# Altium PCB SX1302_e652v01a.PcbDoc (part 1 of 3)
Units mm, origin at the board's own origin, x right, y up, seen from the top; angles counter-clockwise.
Board outline 70.5 x 56 mm, 6 copper layers (Top Layer, MidLayer1 - GND, MidLayer2, MidLayer3, MidLayer4, Bottom Layer), stack 0.992 mm thick; 264 components, 191 nets, 862 pads, 1252 vias.
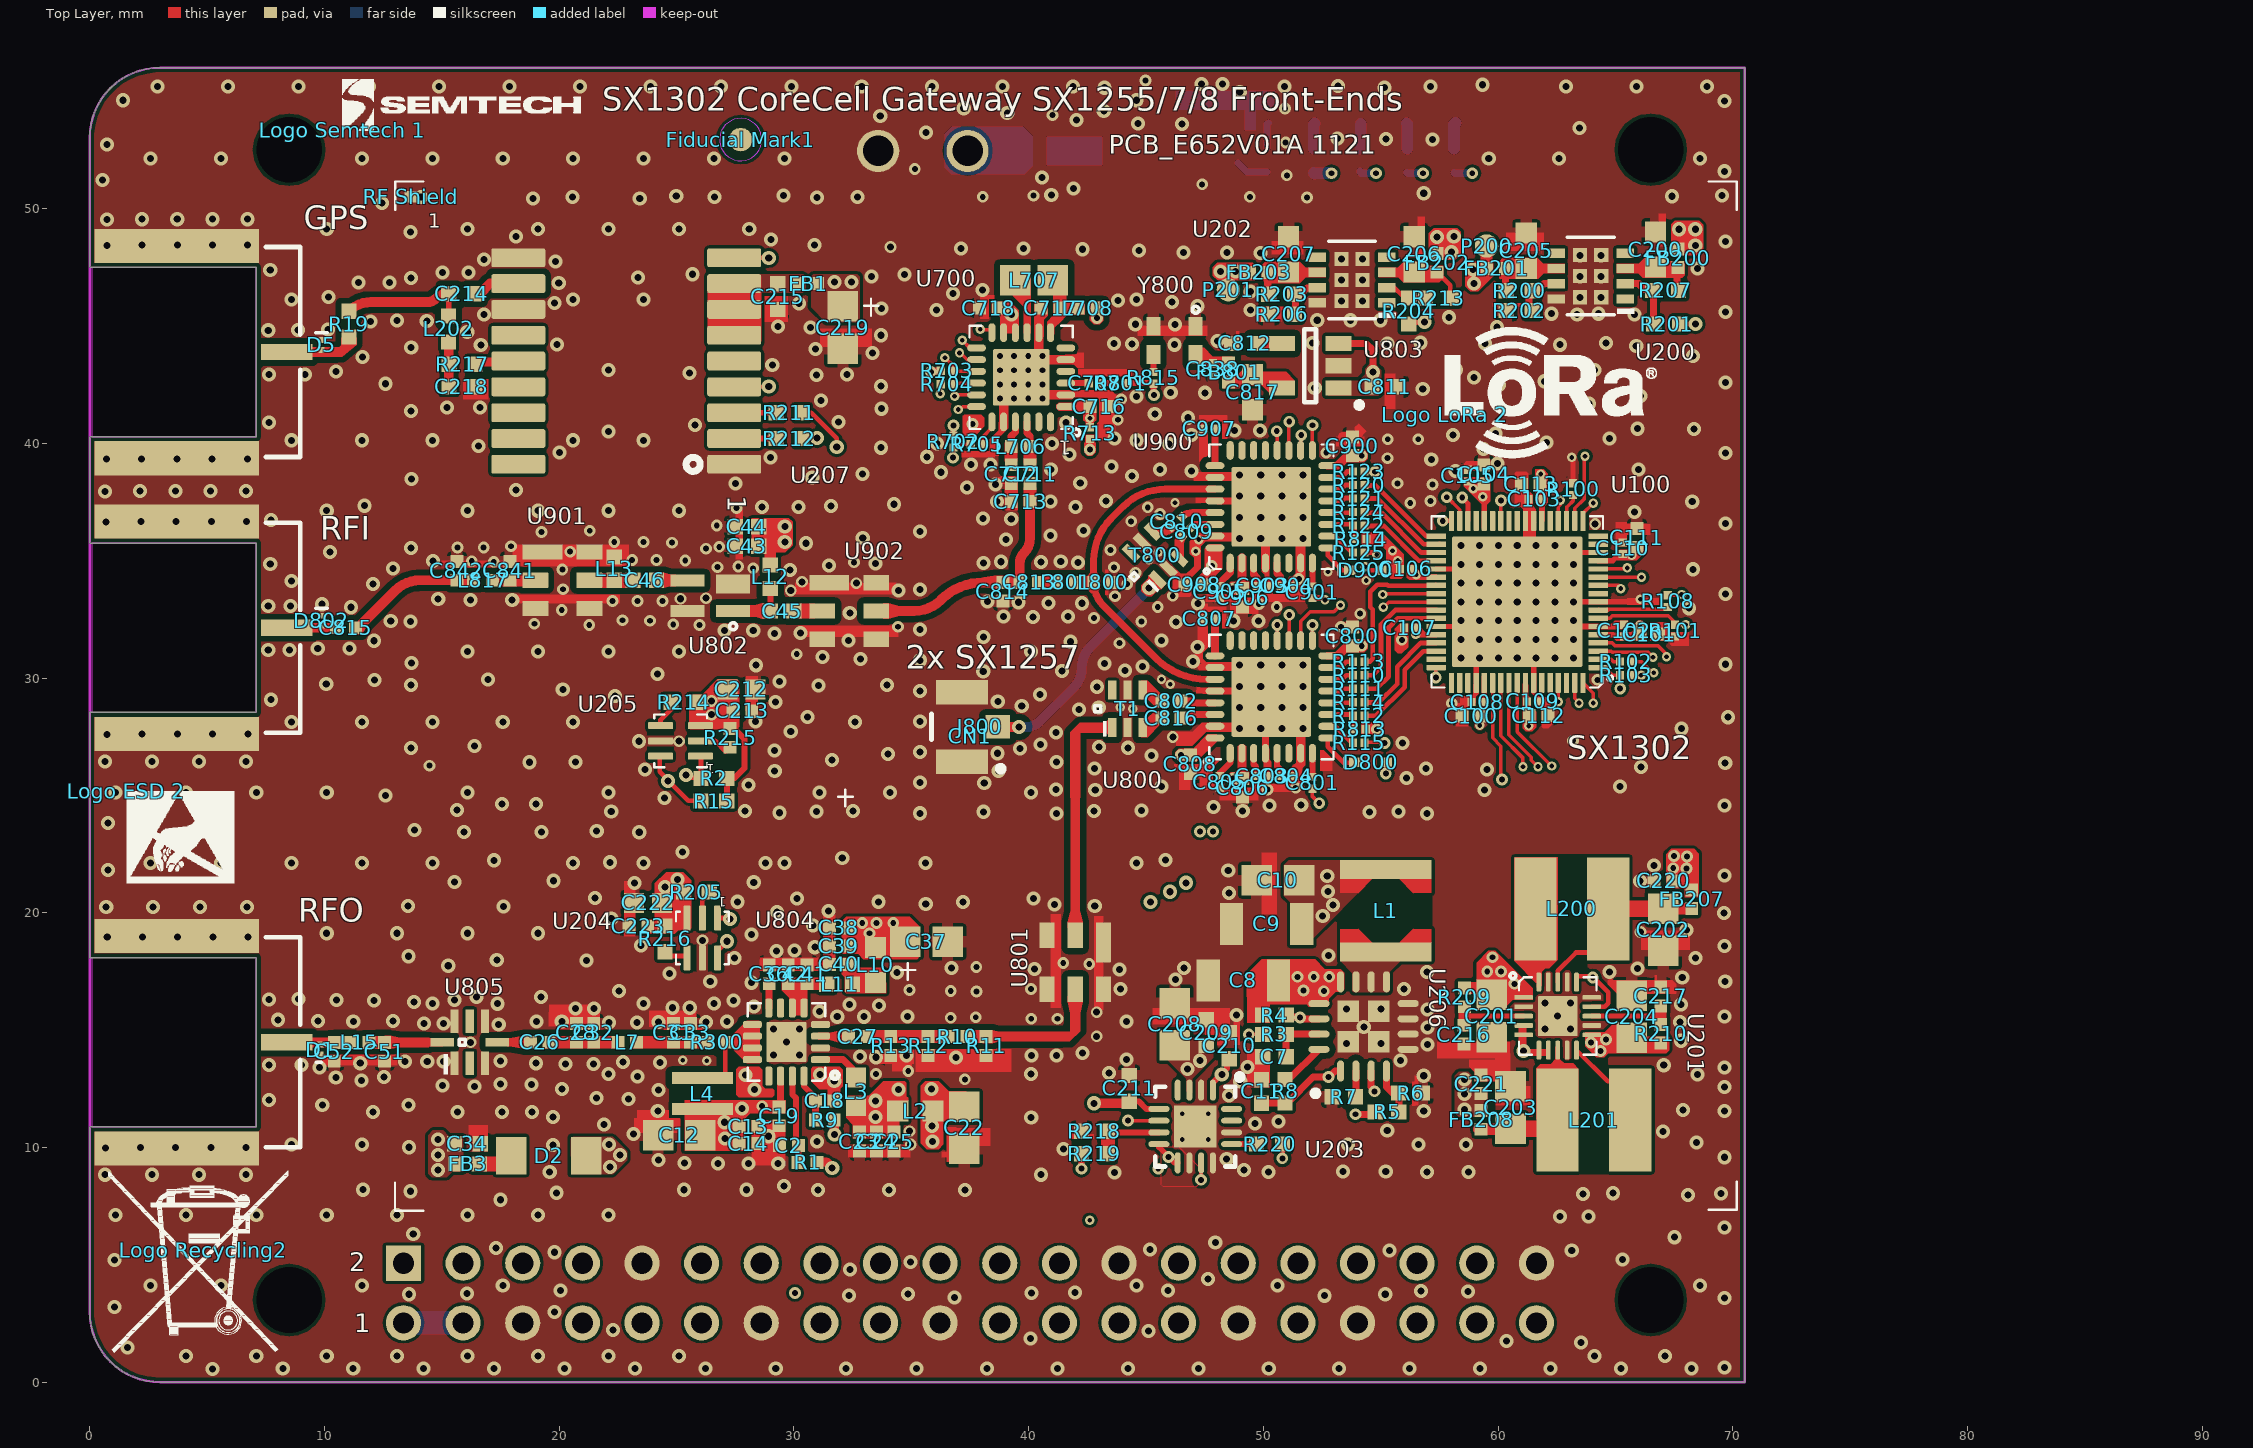
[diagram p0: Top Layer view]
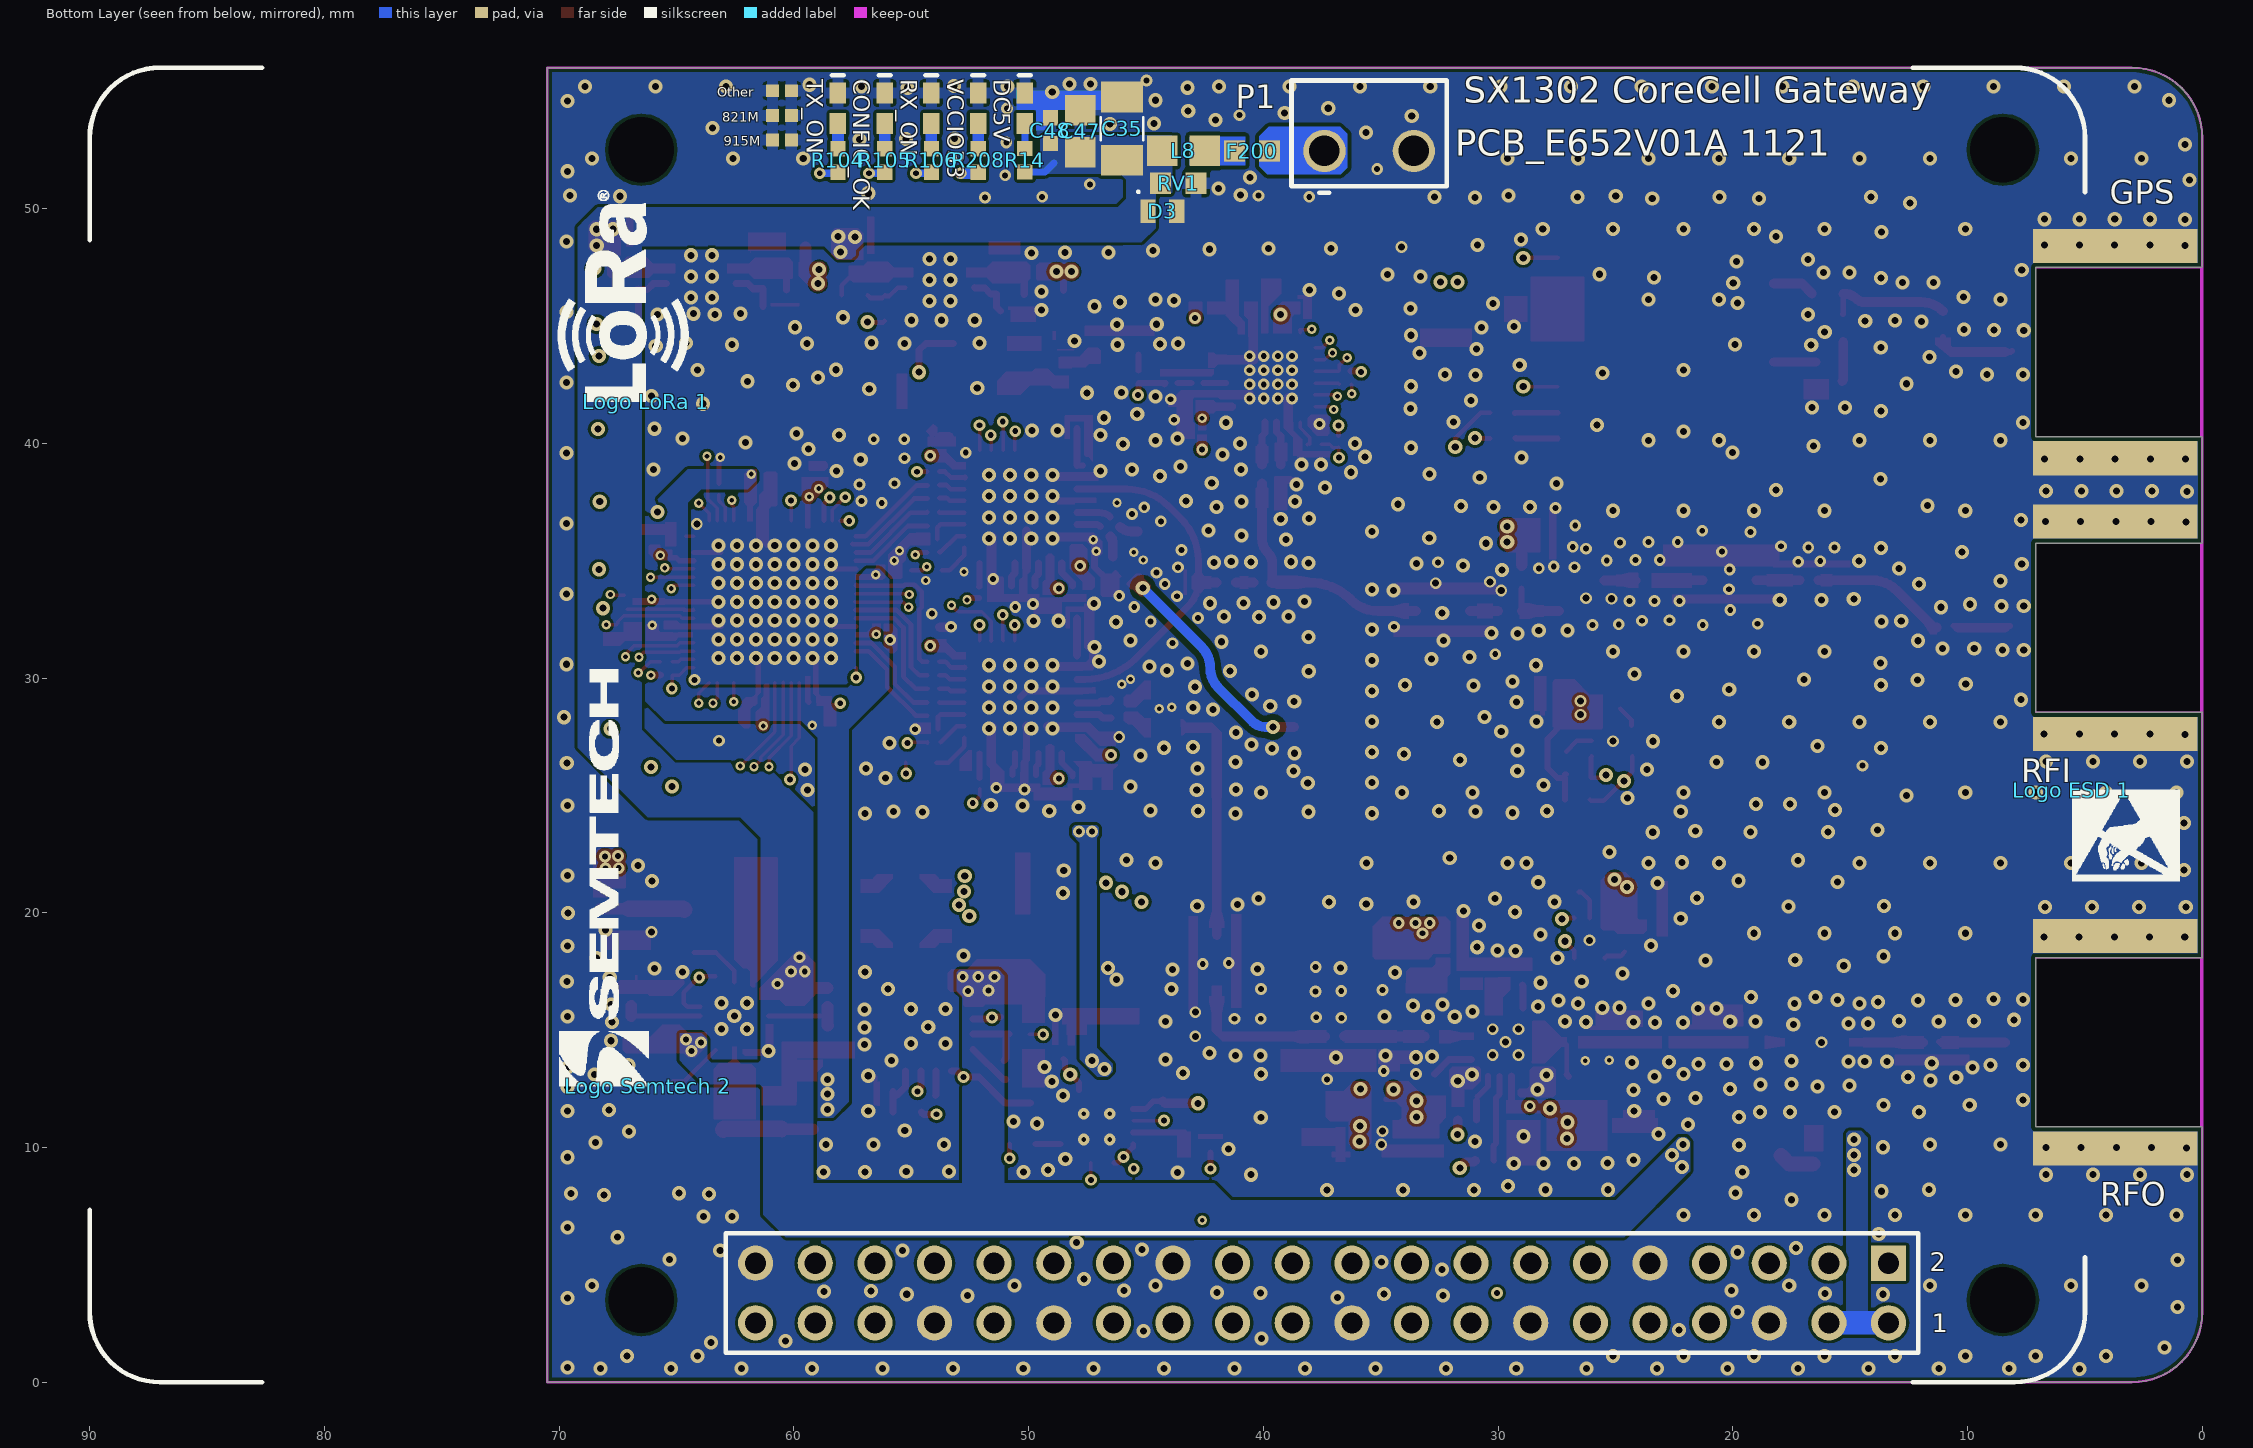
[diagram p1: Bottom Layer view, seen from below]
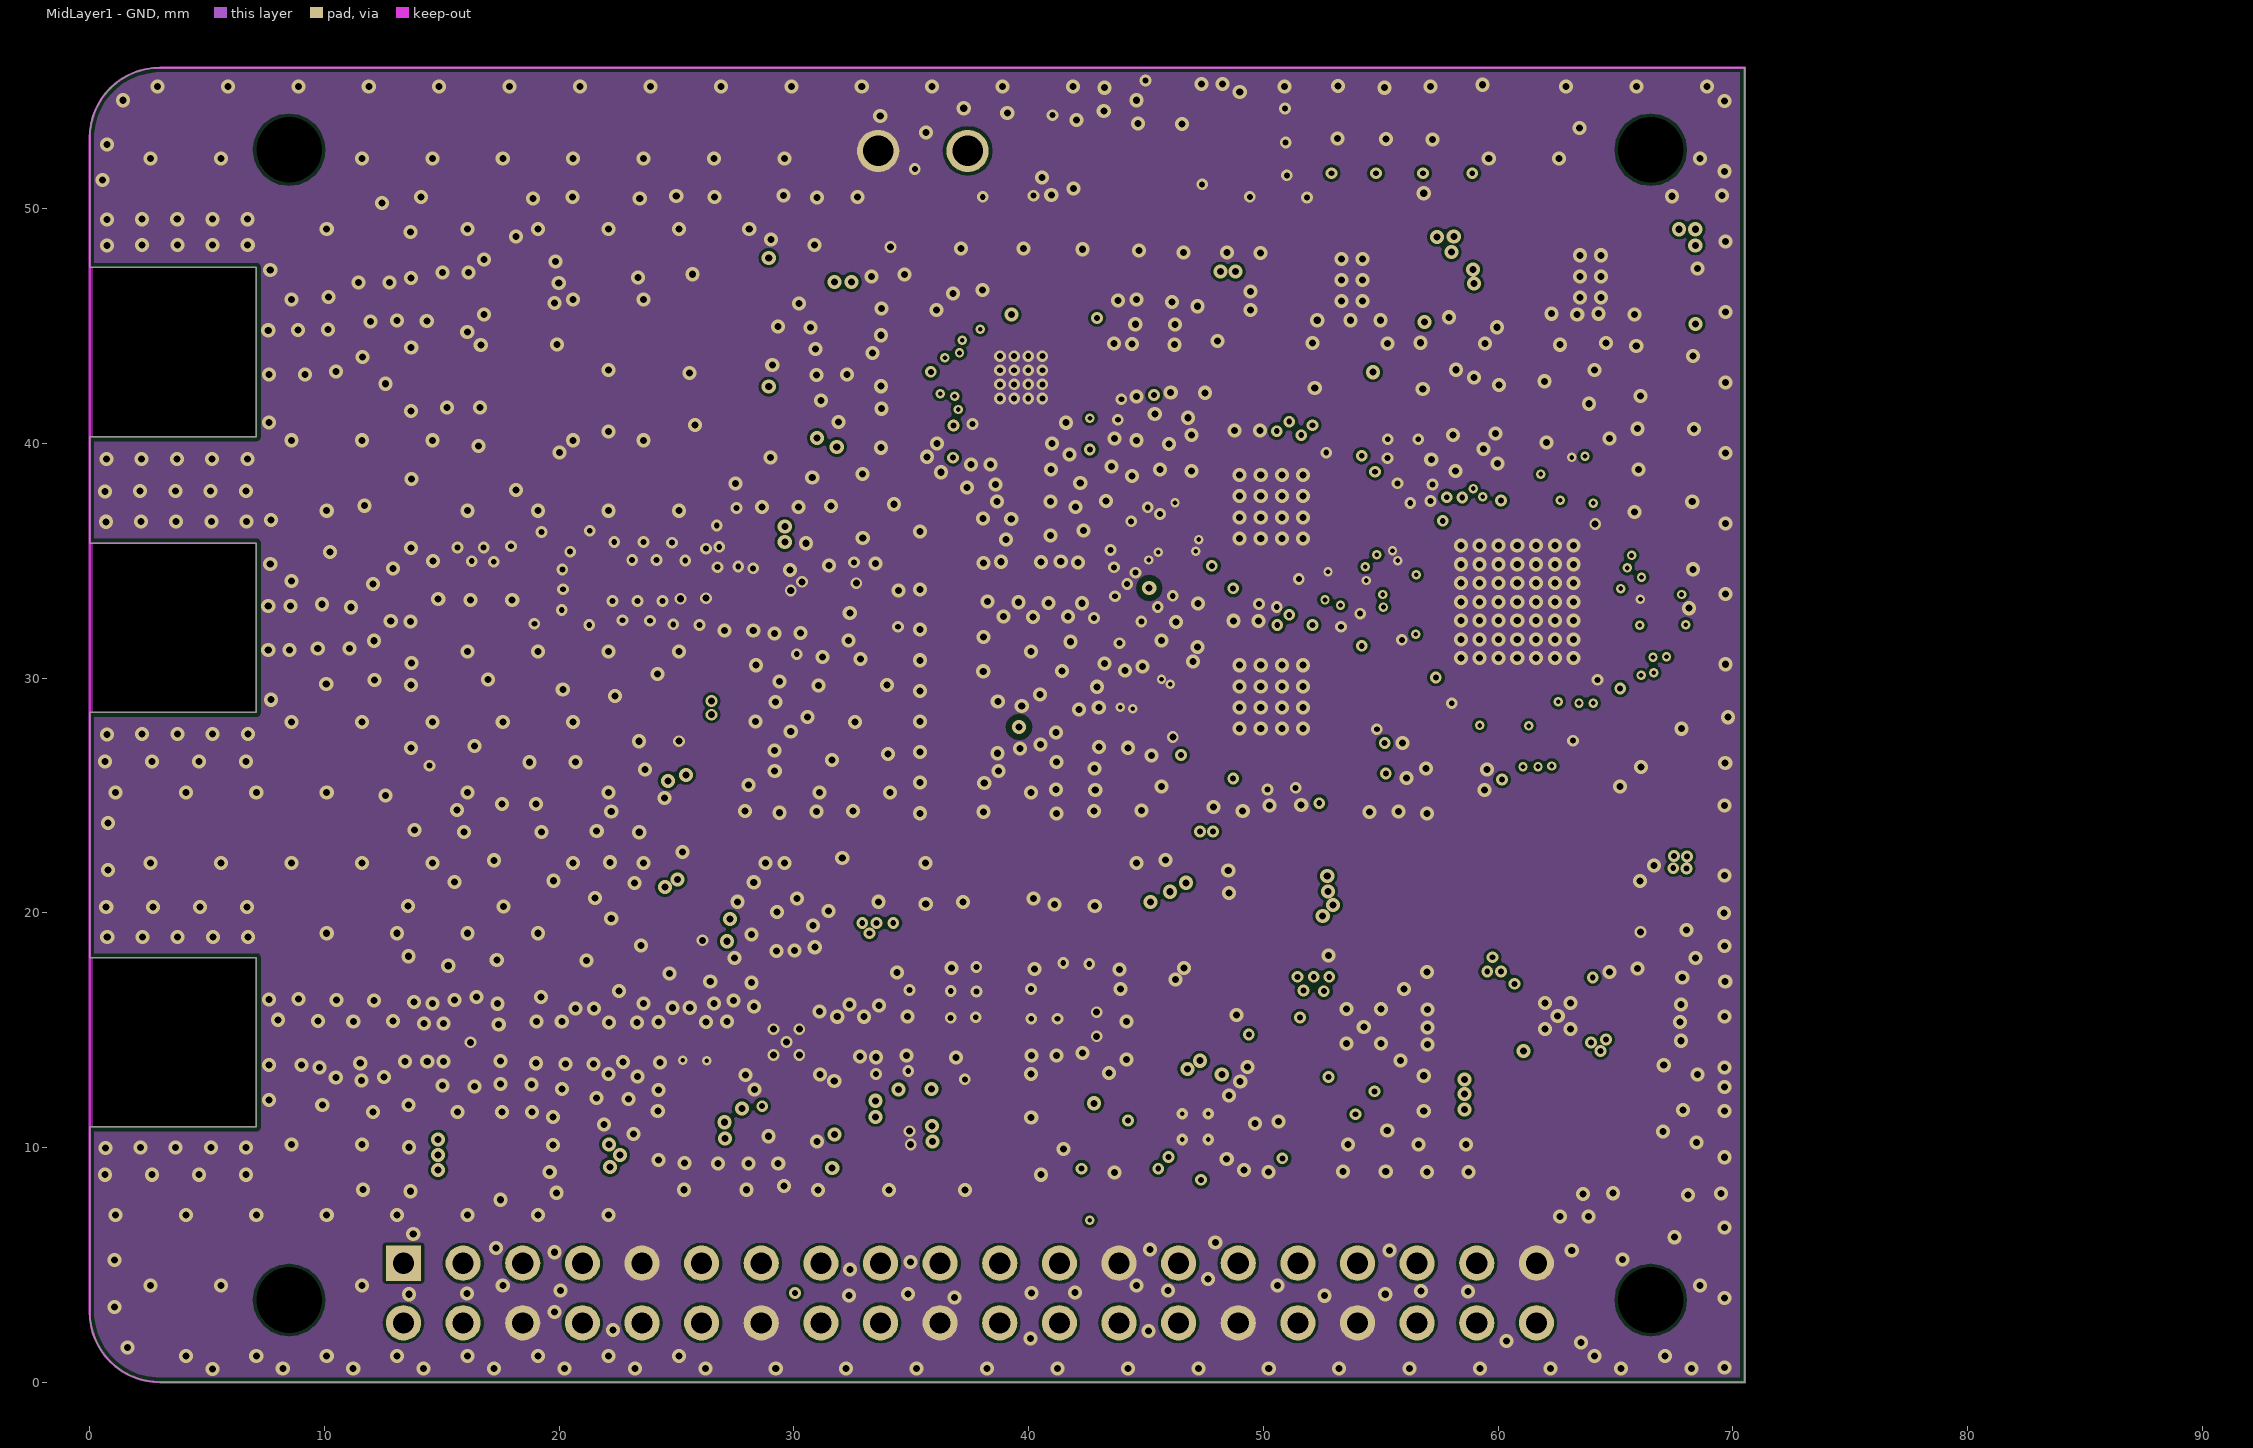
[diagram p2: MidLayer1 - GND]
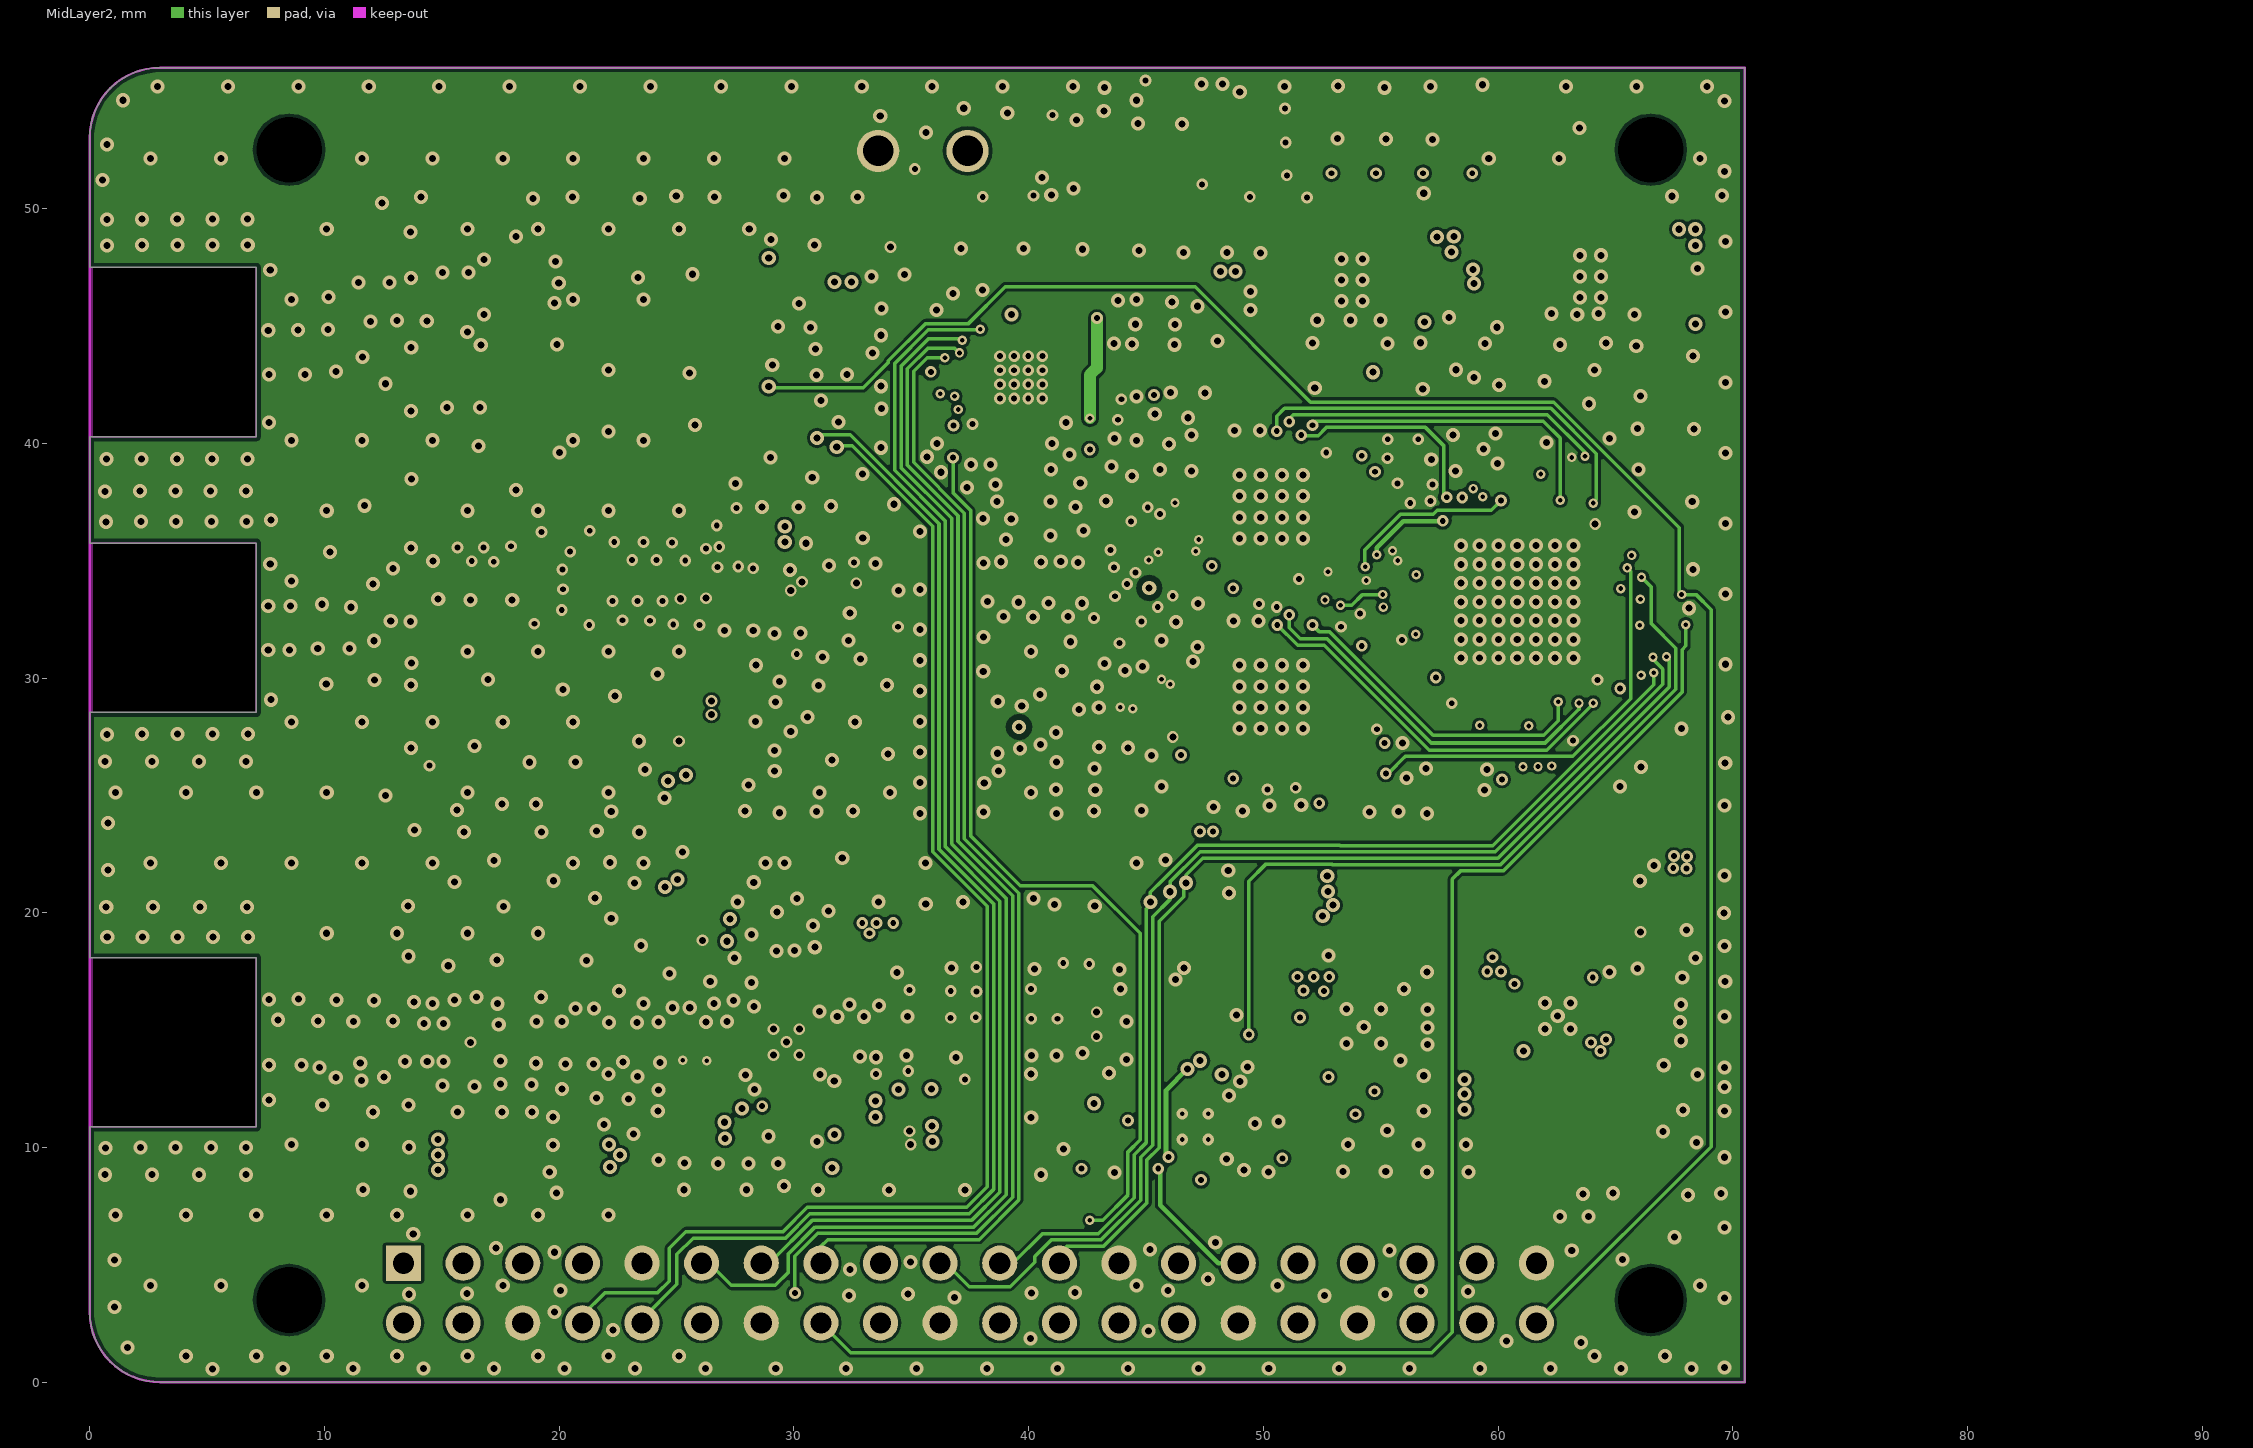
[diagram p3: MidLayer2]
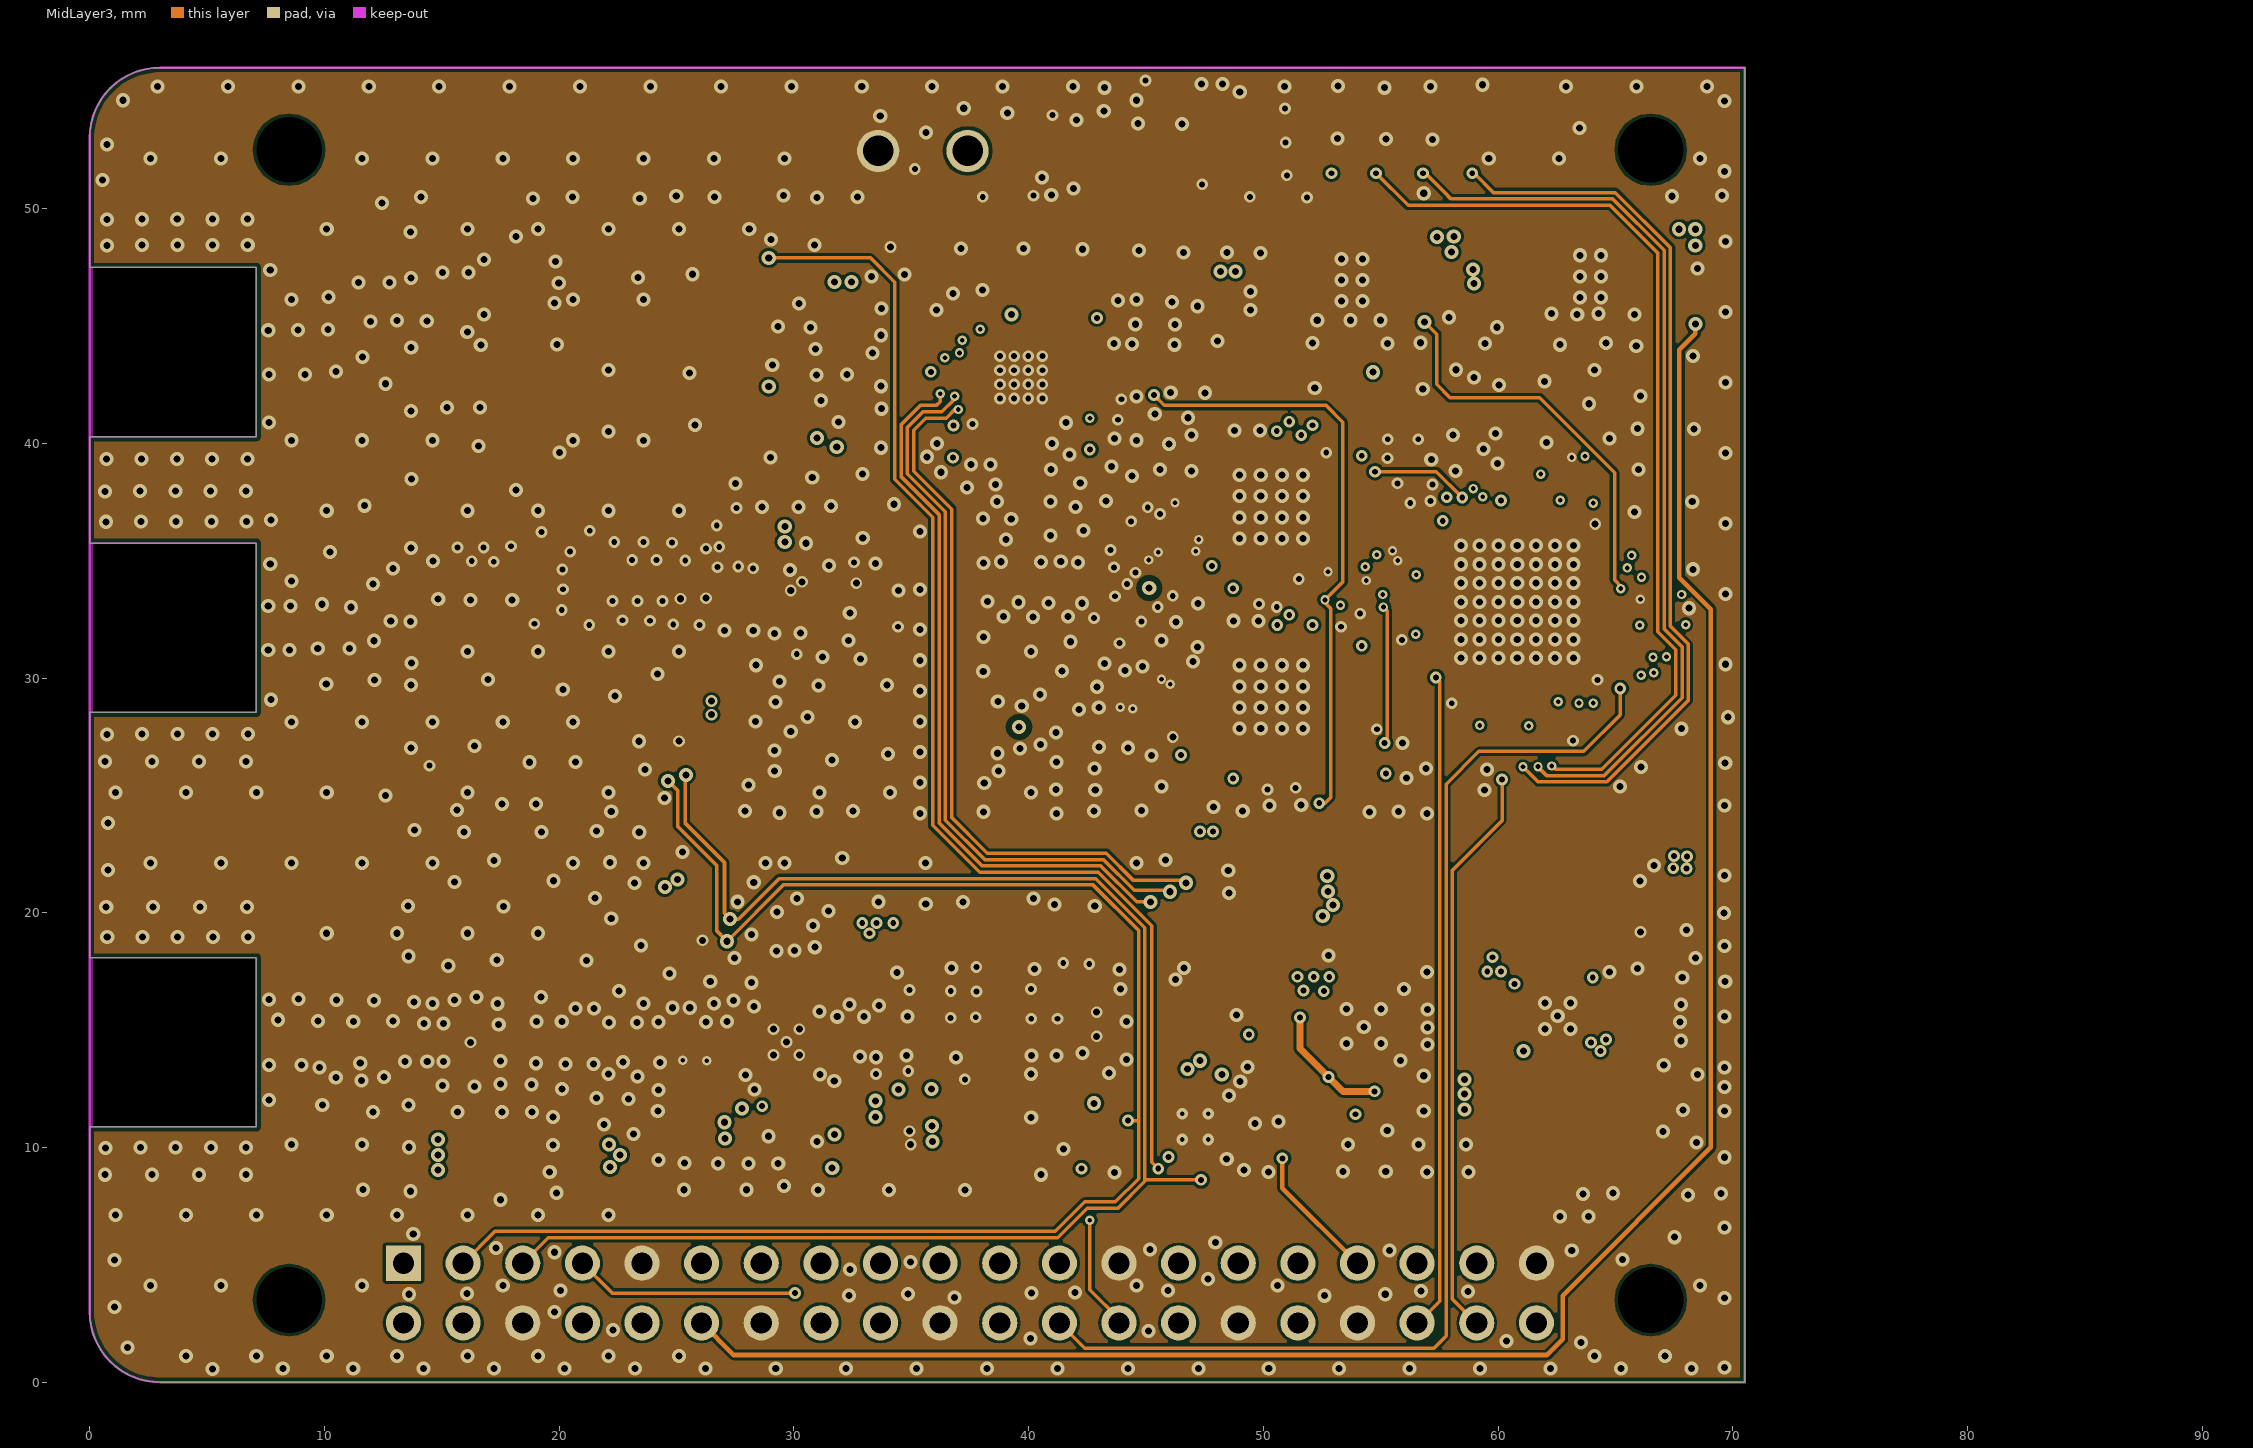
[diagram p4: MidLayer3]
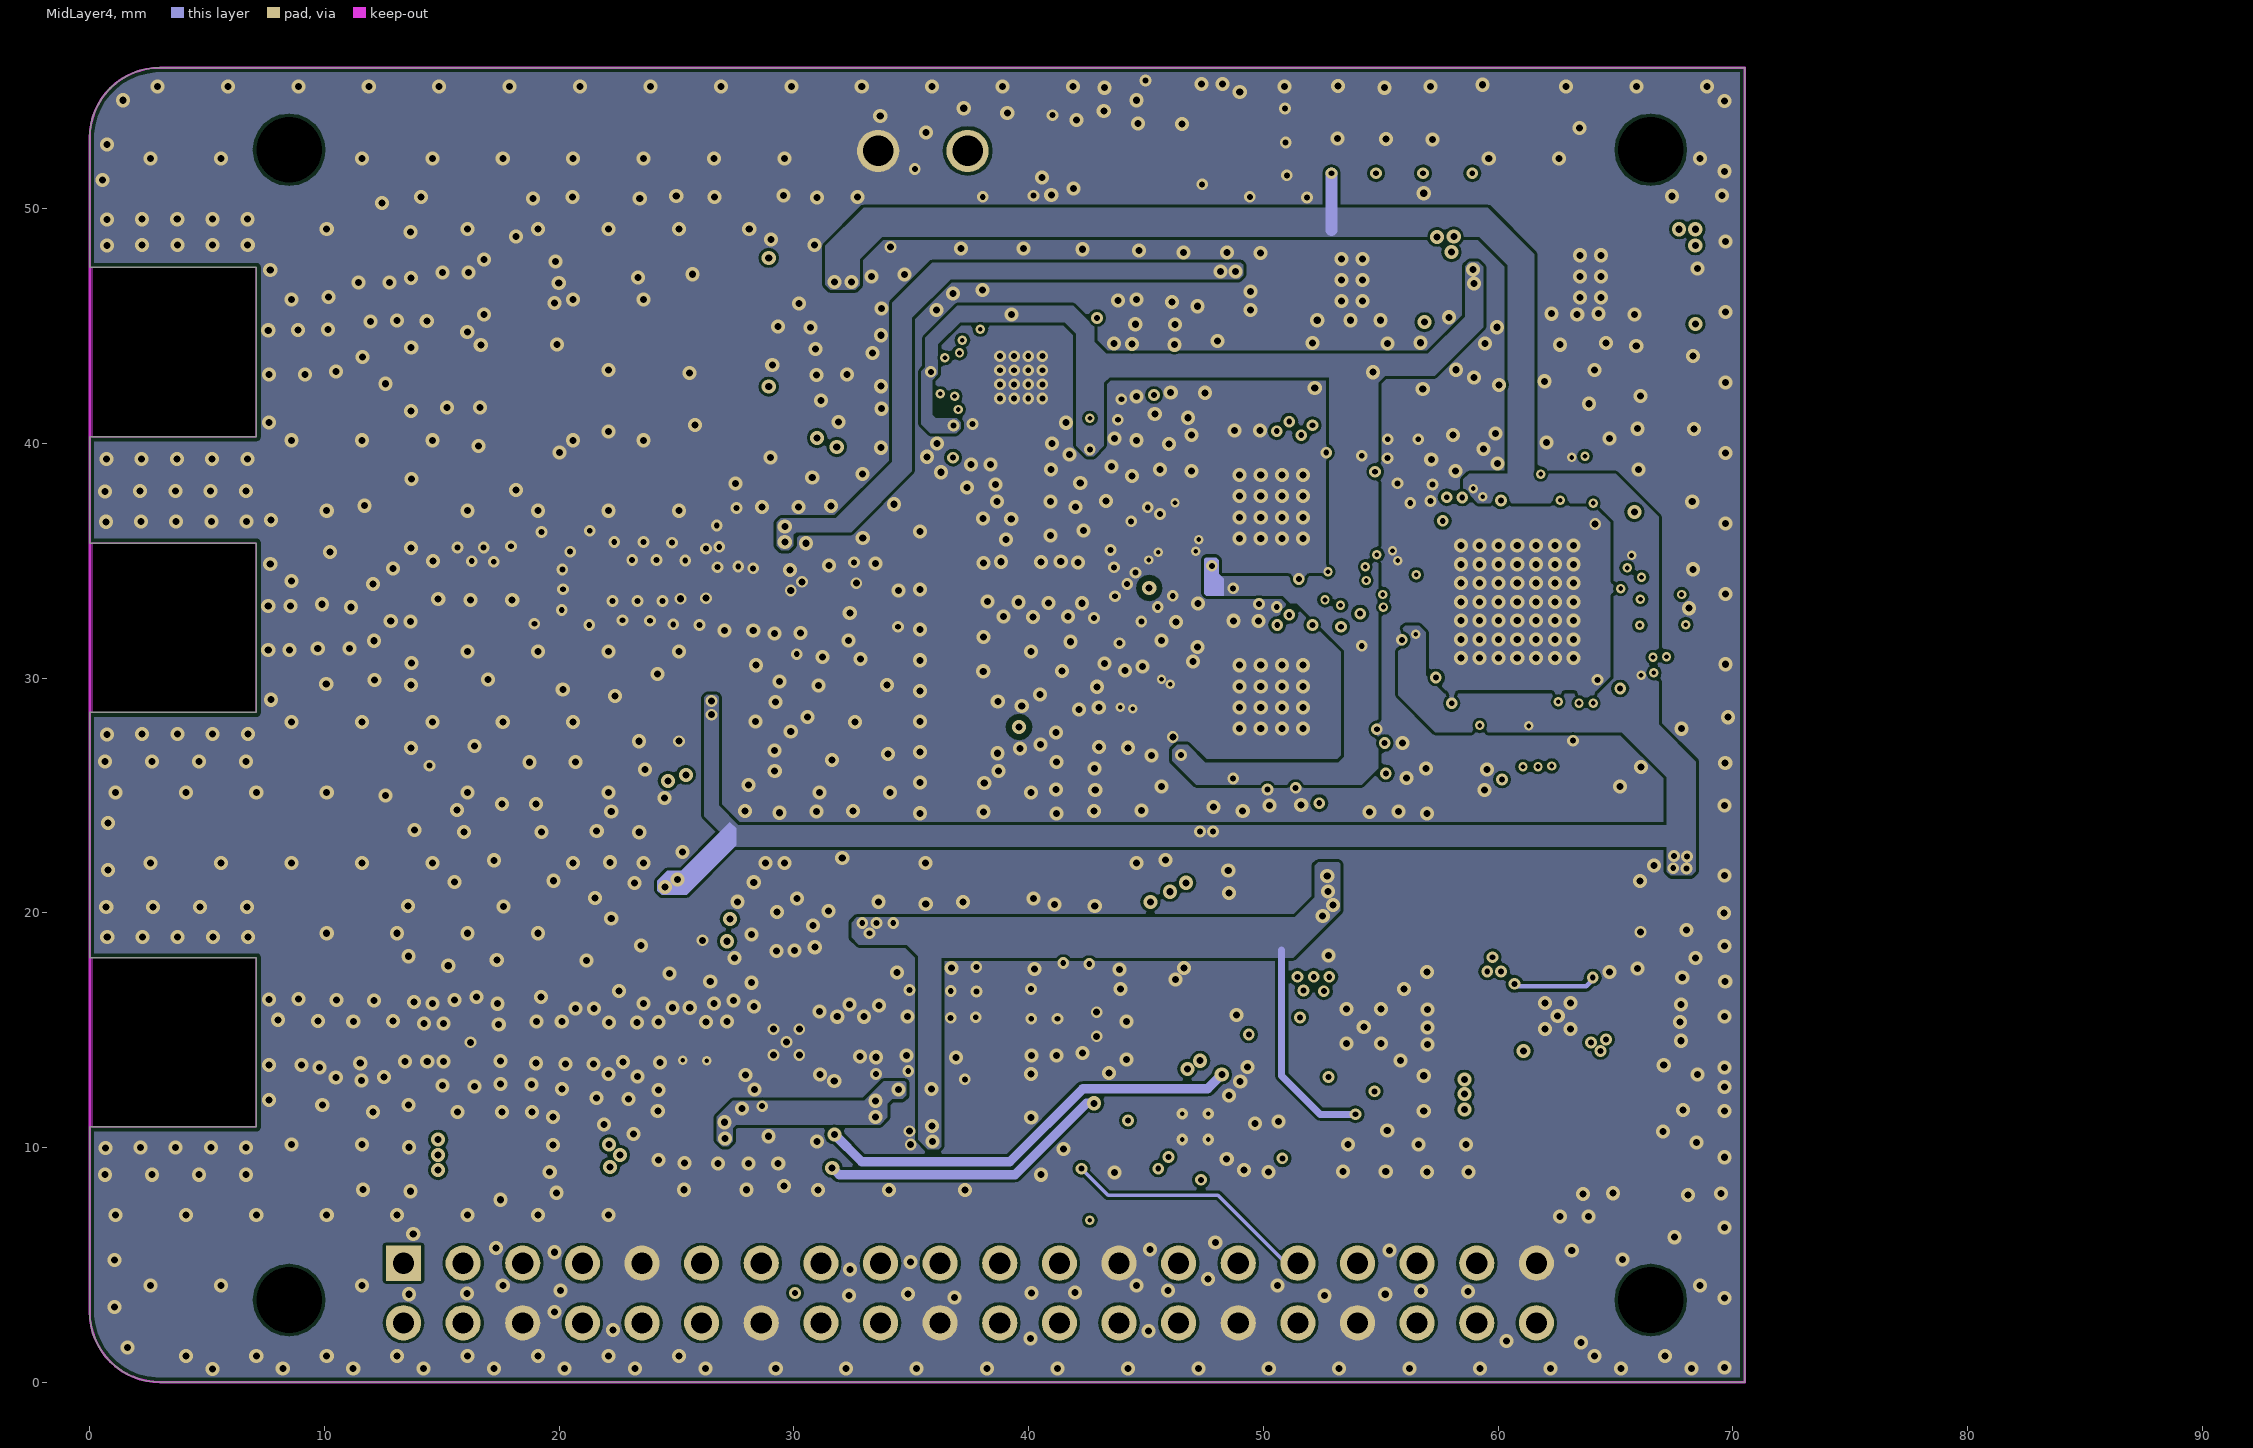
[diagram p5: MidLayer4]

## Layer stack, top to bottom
Top Solder: solder mask 0.0102, Solder Resist, Dk 3.5
Top Layer: signal copper 0.035
Dielectric1: core 0.15, FR-4, Dk 4.3
MidLayer1 - GND: signal copper 0.018
Dielectric 4: prepreg 0.15, FR-4, Dk 4.3
MidLayer2: signal copper 0.018
Dielectric2: core 0.25, FR-4, Dk 4.3
MidLayer3: signal copper 0.018
Dielectric 6: prepreg 0.15, FR-4, Dk 4.3
MidLayer4: signal copper 0.018
Dielectric 5: core 0.15, FR-4, Dk 4.3
Bottom Layer: signal copper 0.035
Bottom Solder: solder mask 0.0102, Solder Resist, Dk 3.5

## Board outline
0.001,2.985 0.001,10.885 7.101,10.885 7.101,18.085 0.001,18.085 0.001,28.545 7.101,28.545 7.101,35.745 0.001,35.745 0.001,40.275 7.101,40.275 7.101,47.49 7.096,47.495 0.001,47.495 0.001,53.005 cw(c3.001,53.005) 3.001,56.005 70.501,56.005 70.501,0.005 3.001,0.005 cw(c3.001,3.005)

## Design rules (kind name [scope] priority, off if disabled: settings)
BoardOutlineClearance [All] p1: gap=0.2 ignorepadtopadclearanceinfootprint=FALSE
Clearance Clearance_RF2 [InNet('NetL800_2')] p1: gap=0.2 ignorepadtopadclearanceinfootprint=FALSE
Clearance Clearance_RF_Area_Bot [(InNet('GND') And (InPolygon)) vs InNet('NetJ800_2')] p2: gap=0.25 ignorepadtopadclearanceinfootprint=FALSE
Clearance Clearance_RF_Area_TOP [InNet('GND') And OnLayer('Top Layer') And (InPolygon) vs InNet('NetC8*')  or  InNet('NetL9*') or InNet('NetC9*') or  InNet('NetL7*') or InNet('NetC7*')  or  InNet('NetU8*') or InNet('NetU9*') or InNet('NetU7*')  or  InNet('NetR8*') or InNet('NetR9*') or  InNet('NetR7*') or InNet('RF*') or InNet('ANT*') or InNet('NetC52*') or InNet('NetC46*') or InNet('NetMOD*') or InNet('NetC28*') or InNet('NetC26*') or InNet('NetC31*') or InNet('NetL4_1*') or InNet('NetC27*') or InNet('NetR10*') or InNet('NetC30*') or InNet('NetC29*') or InNet('TX_PA') or InNet('NetC81*')or InNet('NetC45*') or InNet('NetR10*') or InNet('NetC51*')or InNet('NetC214*') or InNet('NetD5*')] p3: gap=0.25 ignorepadtopadclearanceinfootprint=FALSE
Clearance Clearance_DC_Supply [((InPolygon) and ( InNet('VCCIO33') or InNet('VCCCORE12') or InNet('VCC_FEM') or InNet('VCC_FEM_1') or InNet('VCC_REG_IN') or  InNet('VDD_RF_125x') or  InNet('VDD_RF_126x') or InNet('VCC5V_IN') or  InNet('VCC5V')))  AND InComponentClass('SX1302_e519v01a_Power&Interface') or  InNet('NetF200*')] p4: gap=0.15 ignorepadtopadclearanceinfootprint=FALSE
Clearance Clearance_GND [InNet('GND')] p5: gap=0.12 ignorepadtopadclearanceinfootprint=FALSE
Clearance "Clearance ALL" [All] p6: gap=0.12 ignorepadtopadclearanceinfootprint=FALSE
ComponentClearance "Component Test Pin" [HasFootprint('PIN_SMD')] p1: gap=0.05 collisioncheckmode=3 verticalgap=0.2 showdistances=FALSE
ComponentClearance [All] p2: gap=0.2 collisioncheckmode=3 verticalgap=0.25 showdistances=FALSE
ComponentOrientations [All] p1: allowedrotations=32
DiffPairsRouting [All] p1: maxlimit=0.3 minlimit=0.15 mostfreqgap=0.2 toplayer_minwidth=0.15 toplayer_maxwidth=0.3 toplayer_prefwidth=0.2 midlayer1_minwidth=0.15 midlayer1_maxwidth=0.3 midlayer1_prefwidth=0.2 midlayer2_minwidth=0.15 midlayer2_maxwidth=0.3 midlayer2_prefwidth=0.2 midlayer3_minwidth=0.15 midlayer3_maxwidth=0.3 midlayer3_prefwidth=0.2 midlayer4_minwidth=0.15 midlayer4_maxwidth=0.3 midlayer4_prefwidth=0.2 bottomlayer_minwidth=0.15 bottomlayer_maxwidth=0.3 bottomlayer_prefwidth=0.2 maxuncoupledlength=12.7
HoleSize [All] p1: absolutevalues=TRUE maxlimit=6.5 minlimit=0.2 maxpercent=80.000 minpercent=20.000
HoleToHoleClearance [All] p1: gap=0.2 allowstackedmicrovias=TRUE
Length [All] p1: maxlimit=400 minlimit=0
MinimumAnnularRing [All] p1: minimumring=0.1
MinimumSolderMaskSliver [All] p1: minsoldermaskwidth=0.05
NetsToIgnore [All] p1:
OvershootFalling [All] p1: maximum=1.000
PermittedLayers [All] p1: toplayerpermitted=TRUE bottomlayerpermitted=TRUE
PlaneClearance [All] p1: clearance=0.2
PlaneConnect [All] p1: planeconnectstyle=Direct reliefexpansion=0.2 reliefentries=4 reliefconductorwidth=0.3 reliefairgap=0.2
PolygonConnect PolygonConnect_power_in [HasFootprint('3.81MM-2P-FEMALE')] p1: thpad.connectstyle=Direct thpad.reliefconductorwidth=0.254 thpad.reliefentries=4 thpad.polygonreliefangle="90 Angle" thpad.airgapwidth=0.254 smdpad.connectstyle=Relief smdpad.reliefconductorwidth=0.254 smdpad.reliefentries=4 smdpad.polygonreliefangle="90 Angle" smdpad.airgapwidth=0.254 via.connectstyle=Relief via.reliefconductorwidth=0.254 via.reliefentries=4 via.polygonreliefangle="90 Angle" via.airgapwidth=0.254
PolygonConnect PolygonConnect_Specific_RF [InNet('GND') vs (HasFootprint('DCC6C_3.0x3.0mm') OR HasFootprint('HHM Series 0805') OR HasFootprint('mlpq16_3x3mm'))] p2: connectstyle=Direct reliefconductorwidth=0.254 reliefentries=4 polygonreliefangle="90 Angle" airgapwidth=0.254
PolygonConnect "PolygonConnect DGND 0402 0201" [InNet('GND') vs HasFootprint('rlc_402_smd_small') or HasFootprint('rlc_402_smd') or  HasFootprint('rlc_201_smd_small')or HasFootprint('rlc_201_smd') or HasFootprint('3.81mm-2P-Female')] p3: thpad.connectstyle=Relief thpad.reliefconductorwidth=0.5 thpad.reliefentries=4 thpad.polygonreliefangle="90 Angle" thpad.airgapwidth=0.127 smdpad.connectstyle=Relief smdpad.reliefconductorwidth=0.5 smdpad.reliefentries=4 smdpad.polygonreliefangle="90 Angle" smdpad.airgapwidth=0.127 via.connectstyle=Direct via.reliefconductorwidth=0.5 via.reliefentries=4 via.polygonreliefangle="90 Angle" via.airgapwidth=0.2
PolygonConnect "PolygonConnect GND SMD" [InNet('GND') vs HasFootprint('rlc_603_smd') or HasFootprint('rlc_603_smd_small') or hasFootprint('rlc_805_smd') or  hasFootprint('rlc_805_smd_small') or  HasFootprint('L4818') or  HasFootprint('CD2012-0402') or HasFootprint('CD1608-0603') or  HasFootprint('VQFN68_7X7MM') or HasFootprint('MLPQ-W18') or HasFootprint('HWSON10_3.0X3.0MM') or  HasFootprint('VQFN32_5X5MM')   or  HasFootprint('TCXO 2.0X1.6MM') or HasFootprint('vqfn24_4x4mm')  or  HasFootprint('SLP1006P2T')  or HasFootprint('CD1608-0603')   or HasFootprint('CD3224') or HasFootprint('DFN6_3X3MM')  or  HasFootprint('SKY66423_16P_3X3MM') or  HasFootprint('SKY66420_16P_3X3MM') or  HasFootprint('CD1005-0402') or  HasFootprint('UDFN-6L_2X2mm')   or  HasFootprint('DCC6C_3.0X3.0MM')] p4: thpad.connectstyle=Direct thpad.reliefconductorwidth=0.5 thpad.reliefentries=4 thpad.polygonreliefangle="90 Angle" thpad.airgapwidth=0.2 smdpad.connectstyle=Relief smdpad.reliefconductorwidth=0.5 smdpad.reliefentries=4 smdpad.polygonreliefangle="90 Angle" smdpad.airgapwidth=0.127 via.connectstyle=Direct via.reliefconductorwidth=0.5 via.reliefentries=4 via.polygonreliefangle="90 Angle" via.airgapwidth=0.2
PolygonConnect PolygonConnect_comp_diverse [InNet('GND') vs HasFootprint('pin_1mm') or  HasFootprint('pin_0.9mm')] p5: thpad.connectstyle=Relief thpad.reliefconductorwidth=0.5 thpad.reliefentries=4 thpad.polygonreliefangle="90 Angle" thpad.airgapwidth=0.127 smdpad.connectstyle=Relief smdpad.reliefconductorwidth=0.5 smdpad.reliefentries=4 smdpad.polygonreliefangle="90 Angle" smdpad.airgapwidth=0.127 via.connectstyle=Direct via.reliefconductorwidth=0.5 via.reliefentries=4 via.polygonreliefangle="90 Angle" via.airgapwidth=0.15
PolygonConnect PolygonConnect_all [All] p6: connectstyle=Direct reliefconductorwidth=0.6 reliefentries=4 polygonreliefangle="90 Angle" airgapwidth=0.127
RoomDefinition SX1302_e652v01a_Power&Interface&Sensors [InComponentClass('SX1302_e652v01a_Power&Interface&Sensors')] p1: confinementstyle=ConfineOut formatcopy=TRUE lockcomponents=FALSE outline 128.673,63.842 149.262,63.842 149.262,68.542 128.673,68.542
RoomDefinition "SX1302_e652v01a_Main part" [InComponentClass('SX1302_e652v01a_Main part')] p2: confinementstyle=ConfineOut formatcopy=TRUE lockcomponents=FALSE outline 128.666,56.894 149.197,56.894 149.197,61.93 128.666,61.93
RoomDefinition SX1302_e652v01a_RF_Part [InComponentClass('SX1302_e652v01a_RF_Part')] p3: confinementstyle=ConfineOut formatcopy=TRUE lockcomponents=FALSE outline 128.191,79.532 128.191,69.83 146.86,69.83 146.86,79.507 146.784,79.583
RoomDefinition SX1302_e652v01a_RF_PA [InComponentClass('SX1302_e652v01a_RF_PA')] p4: confinementstyle=ConfineOut formatcopy=TRUE lockcomponents=FALSE outline 128.123,84.759 128.25,85.427 147.377,85.427 147.402,85.56 147.402,80.221 128.149,80.221 128.123,80.354
RoutingVias [All] p1: holewidth=0.25 width=0.5 viastyle="Through Hole" minholewidth=0.2 minwidth=0.4 maxholewidth=1 maxwidth=1
SMDToCorner [All] p1: distance=7874
SilkToSilkClearance [All] p1: silktosilkclearance=0.05
SilkToSolderMaskClearance SilkscreenOverComponentPads [IsPad] p1: minsilkscreentomaskgap=0.05 clearancetoexposedcopper=TRUE
SolderMaskExpansion [All] p1: expansion=0.05
SupplyNets [All] p1: voltage=3.300
ViasUnderSMD [All] p1: allowed=TRUE
Width "Width GND" [InNet('GND')] p1: maxlimit=3 minlimit=0.2 preferedwidth=0.4
Width Width_VCC [InNet('VCCDIG33') or   InNet('VCCDIG18') or  InNet('+5V') or  InNet('VDD5V_USB') or  InNet('VCC_FEM')  or  InNet('VCC_FEM_1')] p2: maxlimit=4 minlimit=0.15 preferedwidth=0.8
Width "Width All" [All] p3: maxlimit=2 minlimit=0.1 preferedwidth=0.15
21 further rules are at their usual default settings.

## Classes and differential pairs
component class "SX1302_e652v01a_Main part": a C100 C101 C102 C103 C104 C105 C106 C107 C108 C109 C110 C111 C112 C113 CONFIG_OK R100 R101 R102 R103 R104 R105 R106 R108 R110 R111 R112 R113 R114 R115 R120 R121 R122 R123 R124 R125 RX_ON SP_VALID SP_VALID_R TX_ON U100
component class SX1302_e652v01a_Power&Interface&Sensors: 5V 821M 915M C7 C8 C9 C10 C11 C34 C35 C47 C48 C200 C201 C202 C203 C204 C205 C206 C207 C208 C209 C210 C211 C212 C213 C214 C215 C216 C217 C218 C219 C220 C221 C222 C223 CN1 D2 D3 D5 DC5V F200 FB1 FB3 FB200 FB201 FB202 FB203 FB207 FB208 "Fiducial Mark1" GPS L1 L8 L200 L201 L202 "Logo ESD 1" "Logo ESD 2" "Logo LoRa 1" "Logo LoRa 2" "Logo Recycling2" "Logo Semtech 1" "Logo Semtech 2" Other P1 P200 P201 R2 R3 R4 R5 R6 R7 R8 R14 R15 R19 R200 R201 R202 R203 R204 R205 R206 R207 R208 R209 R210 R211 R212 R213 R214 R215 R216 R217 R218 R219 R220 RV1 U200 U201 U202 U203 U204 U205 U206 U207 VCCIO33
component class SX1302_e652v01a_RF_Part: C43 C44 C45 C46 C708 C711 C712 C713 C716 C717 C718 C800 C801 C802 C803 C804 C805 C806 C807 C808 C809 C810 C811 C812 C813 C814 C815 C816 C817 C828 C833 C838 C841 C842 C900 C901 C903 C904 C905 C906 C907 C908 D800 D802 D900 FB801 J800 L12 L13 L706 L707 L708 L800 L801 L811 L812 L817 R701 R702 R703 R704 R705 R713 R813 R814 R815 "RF Shield" RFI RFIO_1 T1 T800 U700 U800 U802 U803 U900 U901 U902 Y800
component class SX1302_e652v01a_RF_PA: C2 C12 C13 C14 C18 C19 C22 C23 C24 C25 C26 C27 C28 C31 C32 C33 C36 C37 C38 C39 C40 C41 C42 C51 C52 D1 L2 L3 L4 L7 L10 L11 L15 R1 R9 R10 R11 R12 R13 R300 RFO U801 U804 U805

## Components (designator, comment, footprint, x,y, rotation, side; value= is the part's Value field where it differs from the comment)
821M "Resistor" RLC_402_SMD_SMALL 60.51,53.97 r180 bottom value=NC
915M "Resistor" RLC_402_SMD_SMALL 60.51,52.92 r180 bottom value=0R
C2 "470nF" rlc_402_smd_small 29.791,10.085 r0 top
C7 "56pF/10V" rlc_402_smd#1 50.47,13.869 r0 top
C8 "47uF/6.3V" 1206 47.649,17.118 r0 top
C9 "47uF/6.3V" 1206 48.639,19.525 r0 top
C10 "4.7uF/10V" rlc_805_smd#1 50.621,21.383 r0 top
C11 "100nF/10V" rlc_402_smd#1 49.92,12.394 r270 top
C12 "" rlc_805_smd#1 25.118,10.521 r0 top value=10uF
C13 "1nF/10V" rlc_402_smd_small 28.063,10.894 r180 top
C14 "33pF/10V" rlc_402_smd_small 28.063,10.169 r180 top
C18 "470nF" rlc_402_smd_small 31.315,11.99 r180 top
C19 "" rlc_402_smd_small 29.376,11.33 r90 top value=100pF
C22 "10uF/10V" rlc_805_smd#2 37.258,10.848 r270 top
C23 "10nF" rlc_402_smd_small 32.791,10.258 r90 top
C24 "1nF" rlc_402_smd_small 33.526,10.258 r90 top
C25 "Cap" rlc_402_smd_small 34.261,10.258 r90 top value=27pF
C26 "" rlc_402_smd_small 19.173,14.487 r0 top value=27pF
C27 "" rlc_402_smd_small 32.726,14.73 r0 top value=56pF
C28 "" rlc_402_smd_small 20.734,14.887 r270 top value=12pF
C31 "" rlc_402_smd_small 24.868,14.887 r270 top value=NC
C32 "" rlc_402_smd_small 21.475,14.887 r270 top value=NC
C33 "" rlc_402_smd_small 25.591,14.887 r270 top value=NC
C34 "Cap" rlc_402_smd#2 16.094,10.16 r0 top value=1uF
C35 "293D127X96R3D2TE3" C1206 46.022,53.404 r90 bottom
C36 "" rlc_402_smd_small 28.95,17.379 r270 top value=1.5pF
C37 "10uF/10V" rlc_805_smd#1 35.647,18.772 r180 top
C38 "10nF/10V" rlc_402_smd_small 31.92,19.356 r0 top
C39 "1nF/10V" rlc_402_smd_small 31.92,18.581 r0 top
C40 "" rlc_402_smd_small 31.921,17.802 r0 top value=15pF
C41 "" rlc_402_smd_small 30.56,17.379 r270 top value=27pF
C42 "" rlc_402_smd_small 29.76,17.379 r270 top value=27pF
C43 "100pF/10V" rlc_402_smd#1 28.002,35.621 r0 top
C44 "100nF" rlc_402_smd#1 28.002,36.446 r0 top
C45 "100pF" rlc_402_smd#1 29.497,32.857 r0 top
C46 "100pF" rlc_402_smd#1 23.647,34.163 r0 top
C47 "293D127X96R3D2TE3" rlc_805_smd#1 47.8,53.294 r90 bottom
C48 "293D127X96R3D2TE3" rlc_402_smd#2 49.07,53.32 r90 bottom
C51 "NC" rlc_402_smd_small 12.57,14.08 r90 top
C52 "NC" rlc_402_smd_small 10.423,14.08 r90 top
C100 "Cap" rlc_402_smd_small 58.857,28.373 r0 top value=1uF
C101 "Cap" RLC_402_SMD_SMALL 66.44,31.873 r180 top value=1uF
C102 "Cap" rlc_201_smd_small 65.365,32.023 r270 top value=100nF
C103 "Cap" rlc_201_smd_small 61.541,37.623 r0 top value=100nF
C104 "Cap" RLC_402_SMD_SMALL 59.39,38.673 r270 top value=1uF
C105 "Cap" rlc_201_smd_small 58.715,38.623 r270 top value=100nF
C106 "Cap" rlc_201_smd_small 56.065,34.648 r0 top value=100nF
C107 "Cap" rlc_201_smd_small 56.24,32.148 r0 top value=100nF
C108 "Cap" rlc_201_smd_small 59.112,28.978 r0 top value=100nF
C109 "Cap" rlc_201_smd_small 61.482,29.003 r180 top value=100nF
C110 "Cap" rlc_201_smd_small 65.308,35.532 r270 top value=100nF
C111 "Cap" rlc_402_smd_small 65.911,35.974 r270 top value=1uF
C112 "Cap" rlc_402_smd_small 61.725,28.398 r180 top value=1uF
C113 "Cap" rlc_402_smd_small 61.393,38.248 r0 top value=1uF
C200 "10uF/6.3V" rlc_603_smd 66.701,48.256 r90 top
C201 "Cap" rlc_805_smd#1 59.739,15.602 r270 top value=10uF
C202 "Cap" rlc_805_smd#1 67.03,19.275 r270 top value=22uF
C203 "Cap" rlc_805_smd#1 60.528,11.706 r90 top value=22uF
C204 "Cap" rlc_805_smd#1 65.692,15.577 r90 top value=10uF
C205 "10uF/6.3V" rlc_603_smd 61.201,48.205 r90 top
C206 "10uF/6.3V" rlc_603_smd 56.426,48.053 r90 top
C207 "10uF/6.3V" rlc_603_smd 51.077,48.053 r90 top
C208 "10u" rlc_805_smd#2 46.231,15.255 r270 top
C209 "100nF" rlc_402_smd#2 47.571,14.901 r90 top
C210 "1uF" rlc_402_smd#2 48.543,14.337 r90 top
C211 "1uF" rlc_402_smd#2 44.283,12.522 r90 top
C212 "Cap" rlc_603_smd_small 27.767,29.518 r0 top value=2.2uF
C213 "Cap" rlc_402_smd_small 27.806,28.607 r0 top value=100nF
C214 "47pF" rlc_402_smd#2 15.847,46.373 r0 top
C215 "Cap" rlc_402_smd#2 29.312,46.248 r270 top value=100nF
C216 "Cap" RLC_402_SMD_SMALL 58.547,14.811 r90 top value=100nF
C217 "Cap" RLC_402_SMD_SMALL 66.929,16.437 r270 top value=100nF
C218 "Cap" rlc_402_smd#2 15.859,42.408 r0 top value=47pF
C219 "10u" rlc_805_smd#2 32.091,44.931 r90 top
C220 "Cap" RLC_402_SMD_SMALL 67.049,21.358 r0 top value=100nF
C221 "Cap" RLC_402_SMD_SMALL 59.275,12.7 r270 top value=100nF
C222 "Cap" rlc_603_smd_small 23.792,20.428 r180 top value=2.2uF
C223 "Cap" RLC_402_SMD_SMALL 23.377,19.428 r180 top value=100nF
C708 "Cap" rlc_201_smd_small 42.81,42.564 r0 top value=10pF
C711 "Cap" RLC_402_SMD_SMALL 40.06,38.689 r90 top value=NC
C712 "Cap" RLC_402_SMD_SMALL 39.26,38.689 r90 top value=3.9pF
C713 "Cap" RLC_402_SMD_SMALL 39.66,37.514 r0 top value=NC
C716 "Cap" RLC_402_SMD_SMALL 43.01,41.564 r180 top value=10nF
C717 "Cap" RLC_402_SMD_SMALL 40.935,45.764 r0 top value=470nF
C718 "Cap" RLC_402_SMD_SMALL 38.31,45.764 r0 top value=100nF
C800 "Cap" RLC_402_SMD_SMALL 53.789,31.773 r270 top value=1uF
C801 "Cap" rlc_201_smd_small 52.092,25.532 r90 top value=1nF
C802 "Cap" RLC_402_SMD_SMALL 46.084,29.022 r180 top value=56pF
C803 "Cap" rlc_201_smd_small 49.946,25.827 r180 top value=100nF
C804 "Cap" rlc_201_smd_small 50.966,25.827 r0 top value=100nF
C805 "Cap" rlc_201_smd_small 48.139,25.573 r270 top value=10nF
C806 "Cap" RLC_402_SMD_SMALL 49.114,25.323 r90 top value=1uF
C807 "Cap" rlc_201_smd_small 47.689,32.523 r0 top value=100nF
C808 "Cap" RLC_402_SMD_SMALL 46.889,26.323 r90 top value=1uF
C809 "Cap" rlc_201_smd 46.732,36.241 r225 top value=NC
C810 "Cap" rlc_201_smd 46.313,36.651 r225 top value=NC
C811 "2.2uF/10V" rlc_402_smd#2 55.175,42.405 r180 top
C812 "10nF/10V" rlc_402_smd#2 49.202,44.255 r0 top
C813 "Cap" RLC_402_SMD_SMALL 40.023,34.073 r180 top value=56pF
C814 "Cap" RLC_402_SMD_SMALL 38.906,33.676 r270 top value=6pF
C815 "Cap" RLC_402_SMD_SMALL 10.919,32.143 r180 top value=100pF
C816 "Cap" RLC_402_SMD_SMALL 46.084,28.298 r180 top value=56pF
C817 "4.7uF/10V" rlc_603_smd 49.539,42.179 r90 top
C838 "Cap" rlc_201_smd_small 47.851,43.164 r90 top value=10nF
C841 "Cap" RLC_402_SMD_SMALL 17.904,34.568 r90 top value=NC
C842 "Cap" RLC_402_SMD_SMALL 15.644,34.568 r90 top value=NC
C900 "Cap" RLC_402_SMD_SMALL 53.789,39.873 r270 top value=1uF
C901 "Cap" rlc_201_smd_small 52.092,33.656 r270 top value=1nF
C903 "Cap" rlc_201_smd_small 49.972,33.923 r180 top value=100nF
C904 "Cap" rlc_201_smd_small 50.987,33.923 r0 top value=100nF
C905 "Cap" rlc_201_smd_small 48.139,33.673 r270 top value=10nF
C906 "Cap" RLC_402_SMD_SMALL 49.114,33.423 r90 top value=1uF
C907 "Cap" rlc_201_smd_small 47.689,40.623 r0 top value=100nF
C908 "Cap" RLC_402_SMD_SMALL 47.055,33.977 r0 top value=1uF
CN1 "Raspberry PI 2x20p connector" HDR2X20_RASPBERRY_PI_REVERSED 13.371,51.235 r0 top locked
CONFIG_OK "LED" CD1005-0402 56.135,54.275 r90 bottom
D1 "RClamp2451ZA" SLP0603P 9.825,14.175 r270 top
D2 "D Schottky" SOD123_INV 19.554,9.659 r180 top
D3 "RClamp0571P" 1610 44.302,49.894 r180 bottom
D5 "RClamp2451ZA" SLP0603P 9.878,44.19 r90 top
D800 "D Schottky" SOD523 54.568,26.408 r0 top
D802 "RClamp2451ZA" SLP0603P 9.878,32.441 r90 top
D900 "D Schottky" SOD523 54.339,34.598 r0 top
DC5V "LED" CD1005-0402 50.16,54.275 r90 bottom
F200 "Fuse 1" rlc_603_smd 40.488,52.446 r0 bottom
FB1 "Ferrite beads" rlc_402_smd_small 30.608,46.807 r180 top value=VAL?
FB3 "Ferrite beads" rlc_402_smd#1 16.098,9.304 r0 top value=VAL?
FB200 "Ferrite beads" rlc_402_smd_small 67.663,47.884 r270 top value=VAL?
FB201 "Ferrite beads" rlc_402_smd_small 59.916,47.452 r180 top value=VAL?
FB202 "Ferrite beads" rlc_402_smd_small 57.401,47.687 r270 top value=VAL?
FB203 "Ferrite beads" rlc_402_smd_small 49.806,47.281 r180 top value=VAL?
FB207 "Ferrite beads" RLC_402_SMD_SMALL 68.25,20.577 r90 top value=VAL?
FB208 "Ferrite beads" RLC_402_SMD_SMALL 59.275,11.183 r90 top value=VAL?
FB801 "Ferrite beads" RLC_402_SMD_SMALL 48.517,43.018 r90 top value=VAL?
"Fiducial Mark1" "Logo symbol  BOT" fiducial_mark_signal_top 27.734,52.939 r90 top
GPS "32K242-40ML5" "ROS-32K242-40ML5_V _MODIFIED" 0.099,43.89 r90 top locked
J800 "NC" TECO-1909763-1_V 37.16,27.918 r90 top
L1 "LPS4018-102NLB" L_4x4_COILCRAFT_LPS4018 55.22,18.337 r90 top
L2 "MPZ1608S300A" rlc_603_smd 35.176,11.555 r180 top
L3 "" rlc_603_smd_small 32.651,12.38 r270 top value=11nH
L4 "" 0806SQ-8N9 26.108,12.299 r270 top value=8.6nH
L7 "" rlc_402_smd_small 22.901,14.487 r180 top value=1nH
L8 "BLM21SP700SH1D" rlc_805_smd#1 43.406,52.456 r0 bottom
L10 "" rlc_603_smd 33.476,17.78 r270 top
L11 "" rlc_402_smd#2 31.951,16.955 r180 top value=1.6nH
L12 "LQW15ANR10J00D" rlc_402_smd#1 28.997,34.313 r90 top
L13 "NC" rlc_402_smd#1 22.347,34.663 r270 top
L15 "0R" rlc_402_smd_small 11.497,14.48 r180 top
L200 "Inductor" L4818 63.144,20.164 r90 top value=2.2uH
L201 "Inductor" L4818 64.083,11.173 r270 top value=2.2uH
L202 "Inductor" rlc_402_smd#2 15.293,44.872 r270 top value=27nH
L706 "Inductor" RLC_402_SMD_SMALL 39.66,39.864 r0 top value=33nH
L707 "Inductor" rlc_805_smd_small 40.235,46.939 r180 top value=15uH
L708 "Inductor" RLC_402_SMD_SMALL 42.51,45.764 r180 top value=47nH
L800 "Inductor" RLC_402_SMD_SMALL 43.173,34.073 r180 top value=NC
L801 "Inductor" RLC_402_SMD_SMALL 41.598,34.073 r180 top value=3.9nH
L817 "Inductor" RLC_402_SMD_SMALL 16.761,34.168 r180 top value=0R
"Logo ESD 1" "Logo symbol" ESD_small 5.56,25.227 r180 bottom
"Logo ESD 2" "Logo symbol" ESD_small 1.572,25.176 r0 top
"Logo LoRa 1" "Logo symbol Bot" "Logo LoRa Size2" 66.316,41.763 r90 bottom
"Logo LoRa 2" "Logo symbol TOP" "Logo LoRa Size2" 57.738,41.218 r0 top
"Logo Recycling2" "Logo symbol" Recycle1 4.848,5.618 r0 top
"Logo Semtech 1" "Logo symbol TOP" logo_semtech_horiz_size1 10.767,53.345 r0 top
"Logo Semtech 2" "Logo Semtech  Bot2" logo_semtech_horiz_size2 66.215,12.603 r90 bottom
Other "Resistor" RLC_402_SMD_SMALL 60.51,55.02 r180 bottom value=NC
P1 "DC5V_Ext" 3.81MM-2P-FEMALE 37.402,52.456 r90 bottom
P200 "Testpoint SMD" TESTPUNKT_SMD_1mm 59.509,48.406 r90 top
P201 "Testpoint SMD" TESTPUNKT_SMD_1mm 48.511,46.538 r90 top
R1 "10R" rlc_402_smd_small 30.582,9.368 r0 top
R2 "Resistor" rlc_402_smd#2 26.595,25.725 r0 top value=4.7k
R3 "100R" rlc_402_smd#1 50.47,14.819 r180 top
R4 "10R" rlc_402_smd#1 50.47,15.644 r0 top
R5 "10k" rlc_402_smd#1 55.27,11.519 r180 top
R6 "2k" rlc_402_smd#1 56.273,12.321 r180 top
R7 "53k6" rlc_402_smd#1 53.422,12.17 r0 top
R8 "10k" rlc_402_smd#1 50.927,12.397 r90 top
R9 "100R" rlc_402_smd_small 31.319,11.171 r0 top
R10 "Resistor" rlc_402_smd_small 36.966,14.73 r0 top value=0R
R11 "Resistor" rlc_402_smd_small 38.191,14.329 r90 top value=NC
R12 "Resistor" rlc_402_smd_small 35.716,14.33 r90 top value=NC
R13 "180R" rlc_402_smd_small 34.126,14.33 r90 top value=10k
R14 "1k" rlc_402_smd#1 50.16,52.055 r270 bottom
R15 "Resistor" rlc_402_smd#2 26.595,24.76 r0 top value=4.7k
R19 "0R" rlc_402_smd#2 11.046,45.077 r270 top
R100 "Resistor" rlc_201_smd_small 63.192,38.053 r270 top value=10k
R101 "Resistor" rlc_201_smd_small 67.54,32.023 r90 top value=10k
R102 "Resistor" rlc_201_smd_small 65.44,30.703 r0 top value=100R
R103 "Resistor" rlc_201_smd_small 65.44,30.123 r0 top value=10k
R104 "Resistor" rlc_402_smd#1 58.126,52.051 r270 bottom value=220R
R105 "Resistor" rlc_402_smd#1 56.135,52.051 r270 bottom value=220R
R106 "Resistor" rlc_402_smd#1 54.143,52.051 r270 bottom value=220R
R108 "Resistor" rlc_201_smd_small 67.23,33.278 r270 top value=0R
R110 "Resistor" rlc_201_smd_small 54.064,30.123 r180 top value=0R
R111 "Resistor" rlc_201_smd_small 54.064,29.548 r180 top value=0R
R112 "Resistor" rlc_201_smd_small 54.064,28.398 r180 top value=0R
R113 "Resistor" rlc_201_smd_small 54.064,30.698 r180 top value=0R
R114 "Resistor" rlc_201_smd_small 54.064,28.973 r180 top value=0R
R115 "Resistor" rlc_201_smd_small 54.064,27.248 r180 top value=0R
R120 "Resistor" rlc_201_smd_small 54.064,38.223 r180 top value=0R
R121 "Resistor" rlc_201_smd_small 54.064,37.648 r180 top value=0R
R122 "Resistor" rlc_201_smd_small 54.064,36.498 r180 top value=0R
R123 "Resistor" rlc_201_smd_small 54.064,38.798 r0 top value=0R
R124 "Resistor" rlc_201_smd_small 54.064,37.073 r180 top value=0R
R125 "Resistor" rlc_201_smd_small 54.064,35.348 r0 top value=0R
R200 "68k" rlc_402_smd#2 60.901,46.505 r180 top
R201 "NC" rlc_402_smd#2 67.184,45.08 r0 top
R202 "12k" rlc_402_smd#2 60.901,45.654 r0 top
R203 "68k" rlc_402_smd#2 50.777,46.353 r180 top
R204 "10k" rlc_402_smd#2 56.188,45.637 r270 top
R205 "Resistor" rlc_402_smd#2 25.847,20.885 r180 top value=10k
R206 "12k" rlc_402_smd#2 50.777,45.502 r0 top
R207 "10k" rlc_402_smd#2 67.129,46.512 r180 top
R208 "Resistor" rlc_402_smd#1 52.152,52.051 r90 bottom value=390R
R209 "Resistor" RLC_402_SMD_SMALL 58.564,16.401 r90 top value=1R
R210 "Resistor" RLC_402_SMD_SMALL 66.929,14.849 r270 top value=1R
R211 "Resistor" rlc_402_smd#2 29.795,41.305 r0 top value=0R
R212 "Resistor" rlc_402_smd#2 29.795,40.205 r0 top value=0R
R213 "NC" rlc_402_smd#2 57.46,46.18 r180 top
R214 "Resistor" rlc_402_smd#2 25.317,28.972 r0 top value=20k
R215 "Resistor" rlc_402_smd_small 27.28,27.452 r90 top value=10k
R216 "Resistor" rlc_402_smd#2 24.508,18.888 r90 top value=12k
R217 "Res1" rlc_402_smd#2 15.865,43.371 r0 top value=10R
R218 "0R" rlc_402_smd#2 42.799,10.691 r0 top
R219 "0R" rlc_402_smd#2 42.802,9.733 r180 top
R220 "0R" rlc_402_smd#2 50.262,10.15 r0 top
R300 "" rlc_402_smd_small 26.715,14.487 r0 top value=0R
R701 "Resistor" rlc_201_smd_small 43.91,42.564 r0 top value=220R
R702 "Resistor" rlc_201_smd_small 36.8,40.076 r270 top value=10k
R703 "Resistor" rlc_201_smd_small 36.51,43.089 r0 top value=10k
R704 "Resistor" rlc_201_smd_small 36.51,42.514 r180 top value=100R
R705 "Resistor" rlc_201_smd_small 37.785,39.964 r180 top value=0R
R713 "Resistor" rlc_201_smd_small 42.61,40.438 r90 top value=NC
R813 "Resistor" rlc_201_smd_small 54.114,27.823 r0 top value=10k
R814 "Resistor" rlc_201_smd_small 54.139,35.923 r0 top value=10k
R815 "Resistor" rlc_201_smd_small 45.314,42.79 r90 top value=150R
"RF Shield" "RF Shield" "SMS-461 - SHIELD - CUSTOM" 13.672,50.502 r0 top locked
RFI "32K242-40ML5" "ROS-32K242-40ML5_V _MODIFIED" 0.099,32.143 r90 top locked
RFO "32K242-40ML5" "ROS-32K242-40ML5_V _MODIFIED" 0.099,14.483 r90 top
RV1 "82536259" rlc_603_smd 43.626,51.08 r0 bottom
RX_ON "LED" CD1005-0402 54.143,54.275 r90 bottom
T1 "Balun" "HHM Series 0805" 44.215,28.69 r0 top
T800 "NC" "HHM Series 0805" 45.394,35.225 r45 top
TX_ON "LED" CD1005-0402 58.126,54.275 r90 bottom
U100 "SX1302" VQFN68_7X7MM 60.815,33.248 r180 top locked
U200 "SC4212" "MLPD-8 3x3mm" 63.945,47.124 r180 top
U201 "SC284" "MLPQ-UT-20 3x3" 62.539,15.602 r0 top
U202 "SC4212" "MLPD-8 3x3mm" 53.776,46.956 r180 top
U203 "AD5338R" CP-16-22_M 47.1,10.897 r270 top
U204 "STTS751-0DP3F" UDFN-6L_2X2mm 26.102,18.929 r270 top
U205 "STTS751-0DP3F" UDFN-6L_2X2mm 25.172,27.325 r180 top
U206 "ADP2164ACPZ-R7" QFN127P600-8N 54.268,15.161 r90 top
U207 "MAX-8Q GPS" MAX-7 22.861,43.505 r0 top
U700 "SX1261" vqfn24_4x4mm 39.685,42.814 r180 top locked
U800 "SX125x" VQFN32_5X5MM 50.339,29.198 r90 top locked
U801 "SAW Filter" DCC6C_3.0x3.0mm 41.987,17.895 r270 top value=3x3mm
U802 "SPF5043Z" SOT-343 26.438,33.508 r180 top
U803 "LP2985-30DBVR" SOT23-5 51.996,43.305 r180 top
U804 "RF5110G" mlpq16_3x3mm 29.685,14.495 r180 top
U805 "" "LP Filter Johanson" 16.195,14.487 r0 top value=0915LP15B026E
U900 "SX125x" VQFN32_5X5MM 50.339,37.298 r90 top locked
U901 "SAW Filter" DCC6C_3.0x3.0mm 20.139,34.168 r0 top value=3x3mm
U902 "SAW Filter" DCC6C_3.0x3.0mm 32.357,32.857 r0 top value=3x3mm
VCCIO33 "LED" CD1005-0402 52.152,54.275 r90 bottom
Y800 "TCXO" "TCXO 2.0x1.6mm" 46.214,44.388 r180 top value=32.0MHz

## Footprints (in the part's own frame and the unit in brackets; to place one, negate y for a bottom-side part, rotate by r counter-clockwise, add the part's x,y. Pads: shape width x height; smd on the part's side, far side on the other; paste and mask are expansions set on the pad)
3.81MM-2P-FEMALE [mm]
  round 1.8 hole 1.3: 1(0,0) 2(0,-3.81)
  silkscreen extent -1.78,-5.21 3,1.4
0806SQ-8N9 [mm] "Precision Wire Wound Inductor, 2-Leads, Body 1.63x1.83mm, IPC Medium Density"
  rect 0.51x2.6 smd: 1(-0.66,0) 2(0.66,0)
  body extent -0.89,-1.04 0.89,1.04, height 1.49
1206 [mil]
  rect 39x71 smd mask+3.94: 1(0,0) 2(118,0)
  body extent -7,-31 125,32, height 60
1610 [mm] "DFN, 2-Leads, Body 1.00x1.60mm, Pitch 1.10mm, IPC Low Density"
  rect 0.65x1 smd: 1(-0.613,0) 2(0.613,0)
  silkscreen extent -1.08,0.77 -0.98,0.87, body extent -0.82,-0.53 0.82,0.53, height 0.55
C1206 [mm] "C1206"
  rect 1.3x1.801 smd mask+0.05: 1(-1.35,0) 2(1.35,0)
  silkscreen extent -0.5,-0.9 0.5,0.9
CD1005-0402 [mm] "Chip Diode; Body 1.0 x 0.5 mm (LxW typ)"
  rect 0.9x0.7 smd mask+0.05: 1(-0.65,0) 2(0.65,0)
  silkscreen extent 1.4,-0.25 1.4,0.25
CP-16-22_M [mm] "QFN, 16-Leads, Body 3x3mm, Pitch 0.5mm, Thermal Pad 1.75x1.75mm, IPC Low Density"
  oval 0.9x0.25 smd: 1(-1.55,0.75) 2(-1.55,0.25) 3(-1.55,-0.25) 4(-1.55,-0.75) 9(1.55,-0.75) 10(1.55,-0.25) 11(1.55,0.25) 12(1.55,0.75)
  oval 0.25x0.9 smd: 5(-0.75,-1.55) 6(-0.25,-1.55) 7(0.25,-1.55) 8(0.75,-1.55) 13(0.75,1.55) 14(0.25,1.55) 15(-0.25,1.55) 16(-0.75,1.55)
  rect 1.8x1.8 smd: 17(0,0)
  silkscreen extent -2.23,-1.7 1.7,2.01, body extent -1.55,-1.55 1.55,1.55, height 0.8
DCC6C_3.0x3.0mm [mm] "DCC6C footprint, 3.0x3.0mm optimized"
  rrect5% 1.7x0.65 smd paste+0 mask+0.05: 1(-0.85,1.2)
  rrect5% 1.1x0.65 smd paste+0 mask+0.05: 2(-1.15,0) 3(-1.15,-1.2) 4(1.15,-1.2) 5(1.15,0) 6(1.15,1.2)
  body extent -1.5,-1.5 1.5,1.5, height 1.1
ESD_small [mm]
  silkscreen extent 0.02,-3.89 4.59,0
fiducial_mark_signal_top [mm] "Fiducial mark for automatic assembly"
  round 1 smd paste-2 mask+0.5: 1(0,0)
  Top Layer keep-out circle w0.05: c0,0 r0.9
  body extent -0.9,-0.9 0.9,0.9, height 1
HDR2X20_RASPBERRY_PI_REVERSED [mm] "Connector; Header; 20x2 Position"
  round 0 hole 2.8 unplated paste-2 mask+0.05: 0(-4.87,-47.73) 0(-4.87,1.27) 0(53.13,-47.73) 0(53.13,1.27)
  rect 1.5x1.5 hole 0.9: 1(0,-46.16)
  round 1.5 hole 0.9: 2(0,-48.7) 3(2.54,-46.16) 4(2.54,-48.7) 5(5.08,-46.16) 6(5.08,-48.7) 7(7.62,-46.16) 8(7.62,-48.7) 9(10.16,-46.16) 10(10.16,-48.7) 11(12.7,-46.16) 12(12.7,-48.7) 13(15.24,-46.16) 14(15.24,-48.7) 15(17.78,-46.16) 16(17.78,-48.7) 17(20.32,-46.16) 18(20.32,-48.7) 19(22.86,-46.16) 20(22.86,-48.7) 21(25.4,-46.16) 22(25.4,-48.7) 23(27.94,-46.16) 24(27.94,-48.7) 25(30.48,-46.16) 26(30.48,-48.7) 27(33.02,-46.16) 28(33.02,-48.7) 29(35.56,-46.16) 30(35.56,-48.7) 31(38.1,-46.16) 32(38.1,-48.7) 33(40.64,-46.16) 34(40.64,-48.7) 35(43.18,-46.16) 36(43.18,-48.7) 37(45.72,-46.16) 38(45.72,-48.7) 39(48.26,-46.16) 40(48.26,-48.7)
  body extent -1.45,-50.75 76.6,4.8, height 10
"HHM Series 0805" [mm] "HHM Series 0805; TDK Body 2.00 x 1.25 mm (LxW max)"
  rect 0.35x0.8 smd mask+0.05: 1(-0.65,-0.8) 2(0,-0.8) 3(0.65,-0.8) 4(0.65,0.8) 5(0,0.8) 6(-0.65,0.8)
  silkscreen extent -1.4,-1.17 -0.9,0.13, body extent -1,-0.63 1,0.63, height 1.2
L4818 [mm] "L4818 Size for LPS4018 - 3.9x3.9mm"
  rect 4.4x1.8 smd mask+0.05: 1(0,1.55) 2(0,-1.55)
  body extent -2,-2 2,2, height 2
L_4x4_COILCRAFT_LPS4018 [mm]
  rect 0.8x3.9 smd mask+0.1: 1(0,0) 2(3.505,0)
  Top Layer region: 0.384,-1.949 0.984,-1.949 0.984,-1.174 0.384,-1.174
  Top Layer region: 2.507,-1.951 3.107,-1.951 3.107,-1.176 2.507,-1.176
  Top Layer region: 2.507,1.175 3.107,1.175 3.107,1.95 2.507,1.95
  Top Layer region: 0.384,1.174 0.984,1.174 0.984,1.949 0.384,1.949
  Top Layer region: 0.983,-1.175 0.383,-0.575 0.183,-0.575 0.183,-1.25 0.333,-1.4 0.833,-1.4 0.833,-1.325
  Top Layer region: 2.508,-1.175 3.108,-0.575 3.308,-0.575 3.308,-1.25 3.158,-1.4 2.658,-1.4 2.658,-1.325
  Top Layer region: 2.508,1.175 3.108,0.575 3.308,0.575 3.308,1.25 3.158,1.4 2.658,1.4 2.658,1.325
  Top Layer region: 0.983,1.175 0.383,0.575 0.183,0.575 0.183,1.25 0.333,1.4 0.833,1.4 0.833,1.325
  body extent -0.22,-1.95 3.68,1.95, height 1.7
"Logo LoRa Size2" [mm] "Logo LoRa Size2 - Top Overlay - 9x5.5mm - Registered"
  silkscreen extent 0,-1.83 9.02,3.72, body extent 1.83,-0.05 3.88,1.95, height 0.8
logo_semtech_horiz_size1 [mm] "Logo semtech horizontal - size1 - S"
  silkscreen extent 0,0 10.16,2.16
logo_semtech_horiz_size2 [mm] "Logo semtech horizontal - size2 - M"
  silkscreen extent 0,-0.03 17.78,3.76
"LP Filter Johanson" [mm] "Low Pass Filter ; Body 2.00 x 1.25 mm (LxW max)"
  rect 0.35x1 smd mask+0.05: 1(-0.65,-0.9) 2(0,-0.9) 3(0.65,-0.9) 5(0.65,0.9) 6(0,0.9) 7(-0.65,0.9)
  rect 1x0.35 smd mask+0.05: 4(1.175,0) 8(-1.175,0)
  silkscreen extent -1.12,-1.37 -0.2,0.13, body extent -1,-0.63 1,0.63, height 1.2
MAX-7 [mm] "MAX-7; GPS U-Blox footprint"
  rrect20% 2.3x0.8 smd mask+0.05: 1(4.6,-4.4) 2(4.6,-3.3) 3(4.6,-2.2) 4(4.6,-1.1) 5(4.6,0) 6(4.6,1.1) 7(4.6,2.2) 8(4.6,3.3) 9(4.6,4.4) 10(-4.6,4.4) 11(-4.6,3.3) 12(-4.6,2.2) 13(-4.6,1.1) 14(-4.6,0) 15(-4.6,-1.1) 16(-4.6,-2.2) 17(-4.6,-3.3) 18(-4.6,-4.4)
  silkscreen extent 2.55,-4.7 3.15,-4.1, body extent -4.9,-5.2 4.9,5.2, height 2.95
"MLPD-8 3x3mm" [mm] "MLPD-8; 3.0x3.0mm; 0.65mm pitch"
  rect 0.75x0.4 smd mask+0.1: 1(-1.475,0.975) 2(-1.475,0.325) 3(-1.475,-0.325) 4(-1.475,-0.975) 5(1.475,-0.975) 6(1.475,-0.325) 7(1.475,0.325) 8(1.475,0.975)
  rect 0.6x0.6 smd paste+0 mask+0.1: 9(-0.45,0.9) 9(-0.45,0) 9(-0.45,-0.9) 9(0.45,0.9) 9(0.45,0) 9(0.45,-0.9)
  silkscreen extent -1.87,-1.65 1,1.65, body extent -1.5,-1.5 1.5,1.5, height 1
mlpq16_3x3mm [mm] "16 Leads, Body 3.0x3.0mm, Pitch 0.50mm, MLPQ16"
  rrect50% 0.8x0.3 smd mask+0.05: 1(-1.45,0.75) 2(-1.45,0.25) 3(-1.45,-0.25) 4(-1.45,-0.75) 9(1.45,-0.75) 10(1.45,-0.25) 11(1.45,0.25) 12(1.45,0.75)
  rrect50% 0.3x0.8 smd mask+0.05: 5(-0.75,-1.45) 6(-0.25,-1.45) 7(0.25,-1.45) 8(0.75,-1.45) 13(0.75,1.45) 14(0.25,1.45) 15(-0.25,1.45) 16(-0.75,1.45)
  rrect5% 1.7x1.7 smd paste-1.7 mask+0.05: 17(0,0)
  silkscreen extent -2.22,-1.65 1.65,1.65, body extent -1.5,-1.5 1.5,1.5
"MLPQ-UT-20 3x3" [mm] "MLPQ, 20-Leads, Body 3x3mm, Pitch 0.4mm; Updated footprint"
  rrect50% 0.8x0.2 smd mask+0.05: 1(-1.45,0.8) 2(-1.45,0.4) 3(-1.45,0) 4(-1.45,-0.4) 5(-1.45,-0.8) 11(1.45,-0.8) 12(1.45,-0.4) 13(1.45,0) 14(1.45,0.4) 15(1.45,0.8)
  rrect50% 0.2x0.8 smd mask+0.05: 6(-0.8,-1.45) 7(-0.4,-1.45) 8(0,-1.45) 9(0.4,-1.45) 10(0.8,-1.45) 16(0.8,1.45) 17(0.4,1.45) 18(0,1.45) 19(-0.4,1.45) 20(-0.8,1.45)
  rrect5% 1.7x1.7 smd paste-0.1 mask+0.05: 21(0,0)
  silkscreen extent -2.03,-1.65 1.65,1.84, body extent -1.5,-1.5 1.5,1.5, height 1
QFN127P600-8N [mm] "ADP2164_QFN16"
  oval 0.9x0.3 smd mask+0.1: 1(-1.9,0.975) 2(-1.9,0.325) 3(-1.9,-0.325) 4(-1.9,-0.975) 9(1.9,-0.975) 10(1.9,-0.325) 11(1.9,0.325) 12(1.9,0.975)
  oval 0.3x0.9 smd mask+0.1: 5(-0.975,-1.9) 6(-0.325,-1.9) 7(0.325,-1.9) 8(0.975,-1.9) 13(0.975,1.9) 14(0.325,1.9) 15(-0.325,1.9) 16(-0.975,1.9)
  rect 0.9x0.9 smd mask+0.1: 17(-0.65,-0.65) 17(-0.65,0.65) 17(0.65,-0.65) 17(0.65,0.65)
  silkscreen extent -2.97,1.92 -2.73,2.17, body extent -2.05,-2.05 2.05,2.05, height 1
Recycle1 [mm]
  silkscreen extent -4.03,-4.33 3.61,3.39
rlc_201_smd [mm] "Chip SMD component 201; Body 0.6 x 0.3 mm (LxW typ)"
  rect 0.35x0.35 smd paste+0 mask+0.025: 1(-0.3,0) 2(0.3,0)
  body extent -0.3,-0.15 0.3,0.15, height 0.5
rlc_201_smd_small [mm] "Chip SMD component 201; Body 0.6 x 0.3 mm (LxW typ); small footprint"
  rect 0.35x0.35 smd paste+0 mask+0.025: 1(-0.25,0) 2(0.25,0)
  body extent -0.3,-0.15 0.3,0.15, height 0.5
rlc_402_smd#1 [mm] "Chip SMD component 402; Body 1.0 x 0.5 mm (LxW typ)"
  rect 0.65x0.65 smd mask+0.05: 1(-0.5,0) 2(0.5,0)
  body extent -0.5,-0.25 0.5,0.25, height 0.6
rlc_402_smd#2 [mm] "Chip SMD component 402; Body 1.0 x 0.5 mm (LxW typ)"
  rect 0.65x0.65 smd mask+0.05: 1(-0.55,0) 2(0.55,0)
RLC_402_SMD_SMALL [mm] "Chip SMD component 402; Body 1.0 x 0.5 mm (LxW typ);small footprint"
  rect 0.55x0.55 smd mask+0.025: 1(-0.4,0) 2(0.4,0)
  body extent -0.5,-0.25 0.5,0.25, height 0.6
rlc_402_smd_small [mm] "Chip SMD component 402; Body 1.0 x 0.5 mm (LxW typ);small footprint"
  rect 0.55x0.55 smd mask+0.025: 1(-0.4,0) 2(0.4,0)
  body extent -0.5,-0.25 0.5,0.25, height 0.6
rlc_603_smd [mm] "Chip SMD component 603; Body 1.6 x 0.8mm (LxW typ)"
  rect 0.9x0.9 smd paste+0 mask+0.05: 1(-0.75,0) 2(0.75,0)
rlc_603_smd_small [mm] "Chip SMD component 603; Body 1.6 x 0.8mm (LxW typ); small footprint"
  rect 0.85x0.85 smd paste+0 mask+0.05: 1(-0.6,0) 2(0.6,0)
  body extent -0.8,-0.4 0.8,0.4, height 0.9
rlc_805_smd#1 [mm] "Chip SMD component 805; Body 2.0 x 1.25 mm (LxW typ)"
  rect 1.3x1.3 smd mask+0.05: 1(-0.9,0) 2(0.9,0)
  body extent -1,-0.63 1,0.63, height 1
rlc_805_smd#2 [mm] "Chip SMD component 805; Body 2.0 x 1.25 mm (LxW typ)"
  rect 1.3x1.3 smd mask+0.05: 1(0.9,0) 2(-0.9,0)
rlc_805_smd_small [mm] "Chip SMD component 805; Body 2.0 x 1.25 mm (LxW typ); small footprint"
  rect 1.3x1.3 smd mask+0.05: 1(-0.8,0) 2(0.8,0)
  body extent -1,-0.63 1,0.63, height 1
"ROS-32K242-40ML5_V _MODIFIED" [mm] "SMA Right Angle Jack, Edge Mount, 14.84x8.944x4.00mm, Rosenberger Recommended"
  rect 0.7x2.2 smd: 1(0,-8.3)
  rect 1.45x7 smd: MP(-4.525,-3.62) MP(4.525,-3.62)
  rect 1.45x7 smd far side paste-2: MP(-4.525,-3.62) MP(4.525,-3.62)
  Keep-Out Layer board cut-out: -3.6,-7 3.6,-7 3.6,0 -3.6,0
  silkscreen extent -4.47,-8.87 4.47,-7.4, body extent -4.47,-8.87 4.47,5.97, height 4
SLP0603P [mm] "Chip TVS Diode; Body 1.0 x 0.6 mm (LxW typ)"
  rect 0.25x0.27 smd mask+0.05: 1(-0.212,0) 2(0.212,0)
  silkscreen extent 0.53,-0.18 0.53,0.05, body extent -0.33,-0.13 0.33,0.13, height 0.8
"SMS-461 - SHIELD - CUSTOM" [mm] "SMS-461 - RF Shield EMI Gasket - Standard Surface Mount Shields -  Leader Tech"
  rect 0.5x0.5 smd paste-1 mask+0.05: 1(0,0)
  silkscreen extent -0.66,-43.2 56.5,0.65, body extent -0.25,-0.25 0.25,0.25, height 6
SOD123_INV [mm] "SOD123; Chip Diode; Body  2.7 x 1.6 mm (LxW typ)"
  rect 1.3x1.6 smd mask+0.05: 1(1.6,0) 2(-1.6,0)
SOD523 [mm] "SOD523; Chip Diode; Body 1.2 x 0.8 mm (LxW typ)"
  rect 0.5x0.4 smd mask+0.05: 1(-0.66,0) 2(0.66,0)
  silkscreen extent -1.1,-0.2 -1.1,0.2, body extent -0.6,-0.4 0.6,0.4, height 0.8
SOT23-5 [mm] "SOT23, 5-Leads, Body 2.9x1.6mm, Pitch 0.95mm, Lead Span 2.8mm, IPC Medium Density"
  rect 1.1x0.65 smd mask+0.05: 1(-1.2,0.95) 2(-1.2,0) 3(-1.2,-0.95) 4(1.2,-0.95) 5(1.2,0.95)
  silkscreen extent -2.21,-1.55 0.25,1.8, body extent -0.9,-1.55 0.9,1.55, height 1.45
SOT-343 [mm] "SOT343, 4-Leads, Body 2x1.3 mm, Pitch 1.3mm, Lead Span 2.1mm"
  rect 1.45x0.5 smd mask+0: 1(-0.975,0.65) 3(0.975,-0.65) 4(0.975,0.65)
  rect 1.45x0.8 smd mask+0: 2(-0.975,-0.5)
  silkscreen extent -1.12,1.15 -0.83,1.45, body extent -0.7,-1.1 0.7,1.1, height 1
"TCXO 2.0x1.6mm" [mm] "SMD 2.0x1.6mm for TCXO or VCTCXO"
  rect 0.6x0.8 smd mask+0.05: 1(-0.9,-0.6) 2(0.9,-0.6) 3(0.9,0.6) 4(-0.9,0.6)
  silkscreen extent -1.05,-1.45 -0.75,-1.15, body extent -1,-0.8 1,0.8, height 1
TECO-1909763-1_V [mm] "SMD, 3-Leads, Body 2.6x2.6mm, Height 1.25mm"
  rect 1.05x2.2 smd: 1(-1.475,0) 3(1.475,0)
  rect 1x1.05 smd: 2(0,-1.525)
  silkscreen extent -1.9,-1.78 0.55,1.3, body extent -1.5,-1.55 1.5,1.55, height 1.25
TESTPUNKT_SMD_1mm [mm]
  round 1 smd paste-50 mask+0: 1(0,0)
UDFN-6L_2X2mm [mm] "6 Leads, Body 2x2mm, pitch 0.65mm, UDFN-6L"
  rrect20% 1.05x0.3 smd paste+0 mask+0.05: 1(-0.85,0.65) 2(-0.85,0) 3(-0.85,-0.65) 4(0.85,-0.65) 5(0.85,0) 6(0.85,0.65)
  silkscreen extent -1.12,-1.12 1.12,1.12, body extent -1,-1 1,1, height 0.55
vqfn24_4x4mm [mm] "24 Leads, Body 4.0x4.0mm, Pitch 0.50mm, VQFN24"
  oval 0.8x0.3 smd mask+0.05: 1(-1.9,1.25) 2(-1.9,0.75) 3(-1.9,0.25) 4(-1.9,-0.25) 5(-1.9,-0.75) 6(-1.9,-1.25) 13(1.9,-1.25) 14(1.9,-0.75) 15(1.9,-0.25) 16(1.9,0.25) 17(1.9,0.75) 18(1.9,1.25)
  oval 0.3x0.8 smd mask+0.05: 7(-1.25,-1.9) 8(-0.75,-1.9) 9(-0.25,-1.9) 10(0.25,-1.9) 11(0.75,-1.9) 12(1.25,-1.9) 19(1.25,1.9) 20(0.75,1.9) 21(0.25,1.9) 22(-0.25,1.9) 23(-0.75,1.9) 24(-1.25,1.9)
  rrect5% 2.4x2.4 smd paste-2.5 mask+0.05: 25(0,0)
  Mechanical 15 keep-out lines w0.1: 2.5,2.5 2.5,-2.5 -2.5,-2.5 -2.5,2.5 2.5,2.5
  silkscreen extent -2.5,-2.2 2.2,2.5, body extent -2,-2 2,2, height 1
VQFN32_5X5MM [mm] "32 Leads, Body 5.0x5.0mm, Pitch 0.50mm, VQFN32"
  oval 0.8x0.3 smd mask+0.05: 1(-2.4,1.75) 2(-2.4,1.25) 3(-2.4,0.75) 4(-2.4,0.25) 5(-2.4,-0.25) 6(-2.4,-0.75) 7(-2.4,-1.25) 8(-2.4,-1.75) 17(2.4,-1.75) 18(2.4,-1.25) 19(2.4,-0.75) 20(2.4,-0.25) 21(2.4,0.25) 22(2.4,0.75) 23(2.4,1.25) 24(2.4,1.75)
  oval 0.3x0.8 smd mask+0.05: 9(-1.75,-2.4) 10(-1.25,-2.4) 11(-0.75,-2.4) 12(-0.25,-2.4) 13(0.25,-2.4) 14(0.75,-2.4) 15(1.25,-2.4) 16(1.75,-2.4) 25(1.75,2.4) 26(1.25,2.4) 27(0.75,2.4) 28(0.25,2.4) 29(-0.25,2.4) 30(-0.75,2.4) 31(-1.25,2.4) 32(-1.75,2.4)
  rrect5% 3.4x3.4 smd paste-3.2 mask+0.05: 33(0,0)
  silkscreen extent -2.85,-2.65 2.65,2.85, body extent -2.5,-2.5 2.5,2.5, height 1
VQFN68_7X7MM [mm] "VQFN68 Leads, Body 7.0x7.0mm, Pitch 0.35mm"
  rrect25% 0.85x0.23 smd paste+0 mask+0.025: 1(-3.45,2.8) 2(-3.45,2.45) 3(-3.45,2.1) 4(-3.45,1.75) 5(-3.45,1.4) 6(-3.45,1.05) 7(-3.45,0.7) 8(-3.45,0.35) 9(-3.45,0) 10(-3.45,-0.35) 11(-3.45,-0.7) 12(-3.45,-1.05) 13(-3.45,-1.4) 14(-3.45,-1.75) 15(-3.45,-2.1) 16(-3.45,-2.45) 17(-3.45,-2.8) 35(3.45,-2.8) 36(3.45,-2.45) 37(3.45,-2.1) 38(3.45,-1.75) 39(3.45,-1.4) 40(3.45,-1.05) 41(3.45,-0.7) 42(3.45,-0.35) 43(3.45,0) 44(3.45,0.35) 45(3.45,0.7) 46(3.45,1.05) 47(3.45,1.4) 48(3.45,1.75) 49(3.45,2.1) 50(3.45,2.45) 51(3.45,2.8)
  rrect25% 0.23x0.85 smd paste+0 mask+0.025: 18(-2.8,-3.45) 19(-2.45,-3.45) 20(-2.1,-3.45) 21(-1.75,-3.45) 22(-1.4,-3.45) 23(-1.05,-3.45) 24(-0.7,-3.45) 25(-0.35,-3.45) 26(0,-3.45) 27(0.35,-3.45) 28(0.7,-3.45) 29(1.05,-3.45) 30(1.4,-3.45) 31(1.75,-3.45) 32(2.1,-3.45) 33(2.45,-3.45) 34(2.8,-3.45) 52(2.8,3.45) 53(2.45,3.45) 54(2.1,3.45) 55(1.75,3.45) 56(1.4,3.45) 57(1.05,3.45) 58(0.7,3.45) 59(0.35,3.45) 60(0,3.45) 61(-0.35,3.45) 62(-0.7,3.45) 63(-1.05,3.45) 64(-1.4,3.45) 65(-1.75,3.45) 66(-2.1,3.45) 67(-2.45,3.45) 68(-2.8,3.45)
  rrect2% 5.55x5.55 smd paste-6.6 mask+0.025: 69(0,0)
  silkscreen extent -4.05,-3.65 3.65,3.65, body extent -3.5,-3.5 3.5,3.5, height 0.9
